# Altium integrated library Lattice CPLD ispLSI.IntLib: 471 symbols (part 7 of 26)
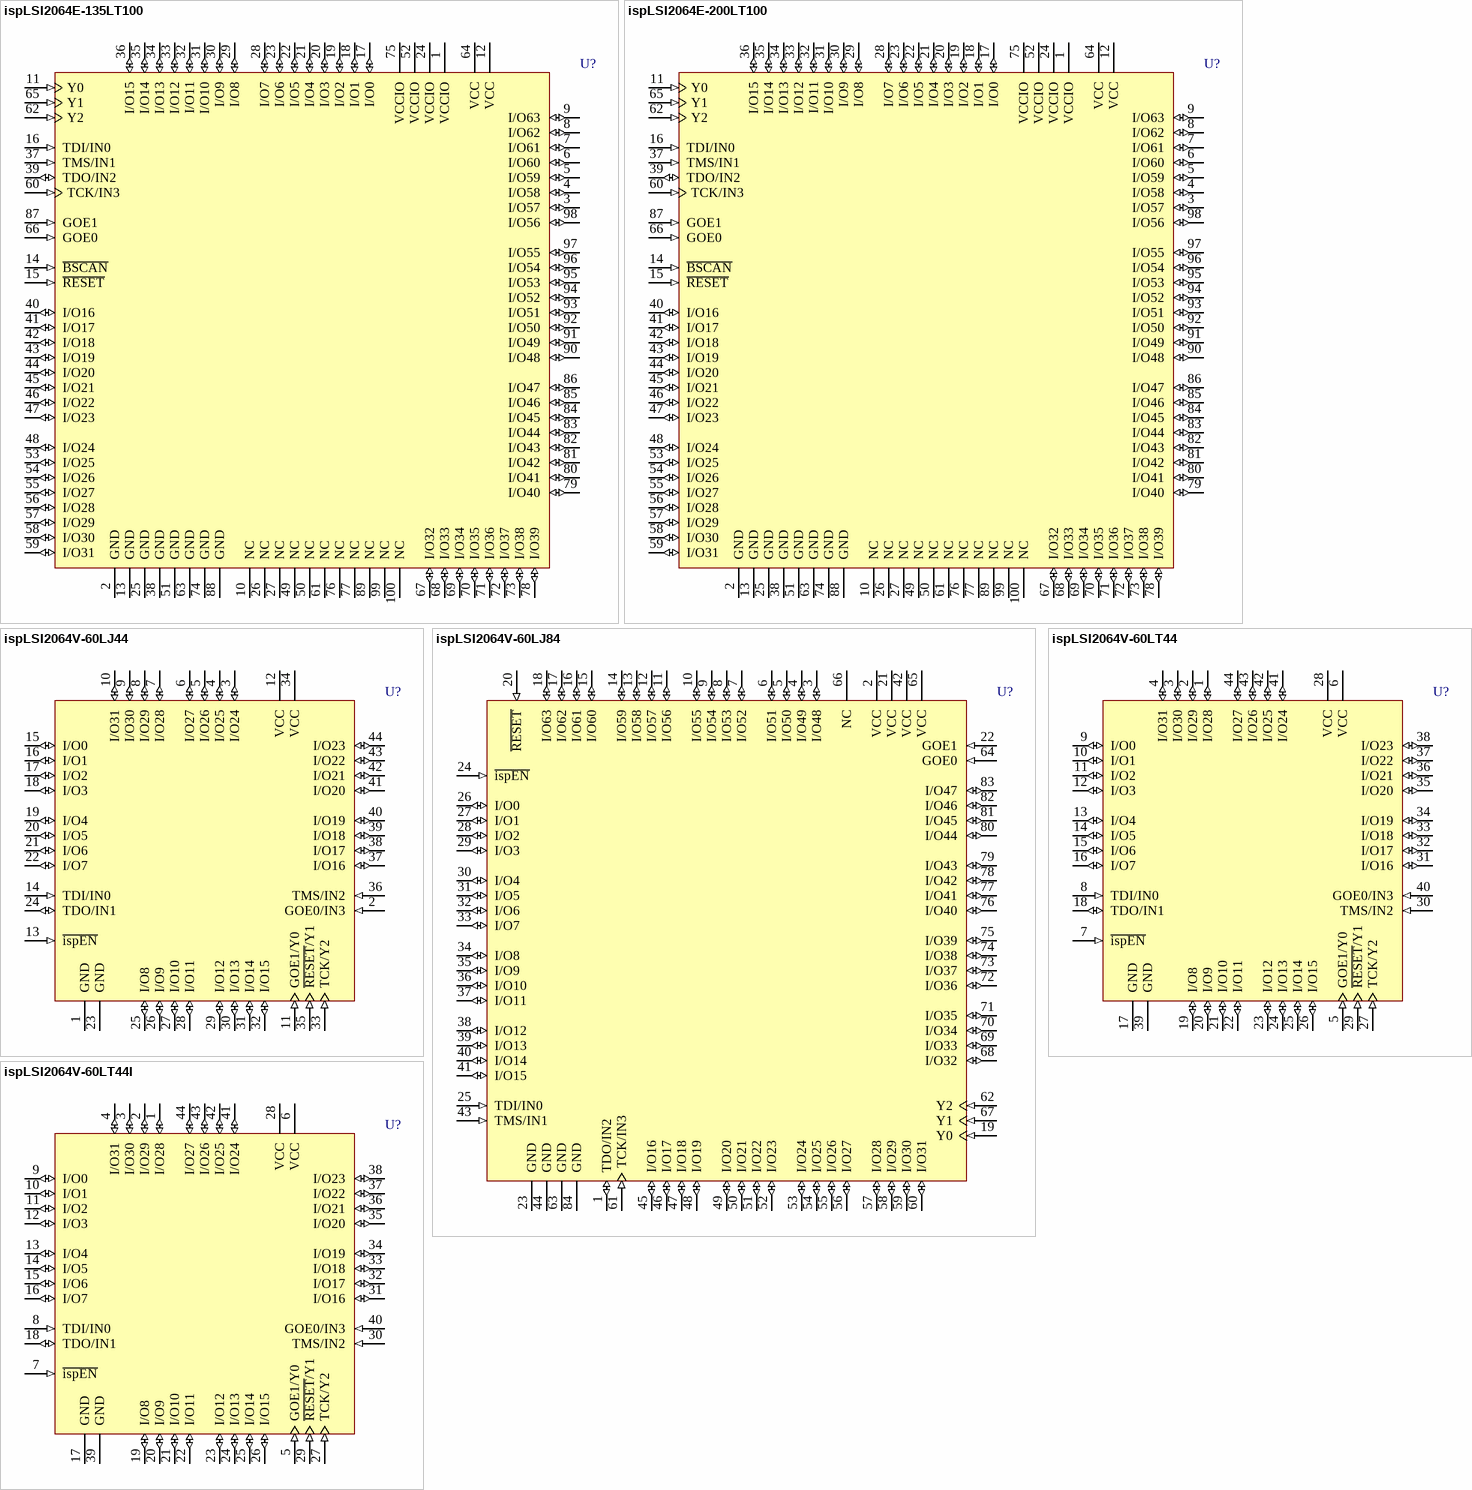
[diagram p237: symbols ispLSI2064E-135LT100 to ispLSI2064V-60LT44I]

## ispLSI2064E-200LT100
designator U?
In-System Programmable SuperFAST High Density PLD
footprint TQFP100_N (Thin QFP, 100-Leads, Body 14x14mm, Pitch 0.5mm, IPC Medium Density)
footprint TQFP100_L (Thin QFP, 100-Leads, Body 14x14mm, Pitch 0.5mm, IPC High Density)
footprint TQFP100_M (Thin QFP, 100-Leads, Body 14x14mm, Pitch 0.5mm, IPC Low Density)
3D model 2064E-TQFP100 (100-Pin Thin Quad Flat Pack (TQFP100))
pins: 1 VCCIO (power), 2 GND (power), 3 I/O57 (io), 4 I/O58 (io), 5 I/O59 (io), 6 I/O60 (io), 7 I/O61 (io), 8 I/O62 (io), 9 I/O63 (io), 10 NC, 11 Y0 (in), 12 VCC (power), 13 GND (power), 14 ~{BSCAN} (in), 15 ~{RESET} (in), 16 TDI/IN0 (in), 17 I/O0 (io), 18 I/O1 (io), 19 I/O2 (io), 20 I/O3 (io), 21 I/O4 (io), 22 I/O5 (io), 23 I/O6 (io), 24 VCCIO (power), 25 GND (power), 26 NC, 27 NC, 28 I/O7 (io), 29 I/O8 (io), 30 I/O9 (io), 31 I/O10 (io), 32 I/O11 (io), 33 I/O12 (io), 34 I/O13 (io), 35 I/O14 (io), 36 I/O15 (io), 37 TMS/IN1 (in), 38 GND (power), 39 TDO/IN2 (io), 40 I/O16 (io), 41 I/O17 (io), 42 I/O18 (io), 43 I/O19 (io), 44 I/O20 (io), 45 I/O21 (io), 46 I/O22 (io), 47 I/O23 (io), 48 I/O24 (io), 49 NC, 50 NC, 51 GND (power), 52 VCCIO (power), 53 I/O25 (io), 54 I/O26 (io), 55 I/O27 (io), 56 I/O28 (io), 57 I/O29 (io), 58 I/O30 (io), 59 I/O31 (io), 60 TCK/IN3 (in), 61 NC, 62 Y2 (in), 63 GND (power), 64 VCC (power), 65 Y1 (in), 66 GOE0 (in), 67 I/O32 (io), 68 I/O33 (io), 69 I/O34 (io), 70 I/O35 (io), 71 I/O36 (io), 72 I/O37 (io), 73 I/O38 (io), 74 GND (power), 75 VCCIO (power), 76 NC, 77 NC, 78 I/O39 (io), 79 I/O40 (io), 80 I/O41 (io), 81 I/O42 (io), 82 I/O43 (io), 83 I/O44 (io), 84 I/O45 (io), 85 I/O46 (io), 86 I/O47 (io), 87 GOE1 (in), 88 GND (power), 89 NC, 90 I/O48 (io), 91 I/O49 (io), 92 I/O50 (io), 93 I/O51 (io), 94 I/O52 (io), 95 I/O53 (io), 96 I/O54 (io), 97 I/O55 (io), 98 I/O56 (io), 99 NC, 100 NC

## ispLSI2064V-60LJ44
designator U?
3.3V High-Density Programmable Logic
footprint PLCC44_N (Leaded Chip Carrier, 44-Leads, Body 16.6x16.6mm, Pitch 1.27mm, IPC Medium Density)
footprint PLCC44_L (Leaded Chip Carrier, 44-Leads, Body 16.6x16.6mm, Pitch 1.27mm, IPC High Density)
footprint PLCC44_M (Leaded Chip Carrier, 44-Leads, Body 16.6x16.6mm, Pitch 1.27mm, IPC Low Density)
3D model 2064V-PLCC44 (44-Pin Leaded Chip Carrier 1.27 mm Pitch)
pins: 1 GND (power), 2 GOE0/IN3 (in), 3 I/O24 (io), 4 I/O25 (io), 5 I/O26 (io), 6 I/O27 (io), 7 I/O28 (io), 8 I/O29 (io), 9 I/O30 (io), 10 I/O31 (io), 11 GOE1/Y0 (in), 12 VCC (power), 13 ~{ispEN} (in), 14 TDI/IN0 (in), 15 I/O0 (io), 16 I/O1 (io), 17 I/O2 (io), 18 I/O3 (io), 19 I/O4 (io), 20 I/O5 (io), 21 I/O6 (io), 22 I/O7 (io), 23 GND (power), 24 TDO/IN1 (io), 25 I/O8 (io), 26 I/O9 (io), 27 I/O10 (io), 28 I/O11 (io), 29 I/O12 (io), 30 I/O13 (io), 31 I/O14 (io), 32 I/O15 (io), 33 TCK/Y2 (in), 34 VCC (power), 35 ~{RESET}/Y1 (in), 36 TMS/IN2 (in), 37 I/O16 (io), 38 I/O17 (io), 39 I/O18 (io), 40 I/O19 (io), 41 I/O20 (io), 42 I/O21 (io), 43 I/O22 (io), 44 I/O23 (io)

## ispLSI2064V-60LJ84
designator U?
3.3V High-Density Programmable Logic
footprint PLCC84_N (Leaded Chip Carrier, 84-Leads, Body 29.3x29.3mm, Pitch 1.27mm, IPC Medium Density)
footprint PLCC84_L (Leaded Chip Carrier, 84-Leads, Body 29.3x29.3mm, Pitch 1.27mm, IPC High Density)
footprint PLCC84_M (Leaded Chip Carrier, 84-Leads, Body 29.3x29.3mm, Pitch 1.27mm, IPC Low Density)
3D model 2064V-PLCC84 (84-Pin Leaded Chip Carrier 1.27 mm Pitch)
pins: 1 TDO/IN2 (io), 2 VCC (power), 3 I/O48 (io), 4 I/O49 (io), 5 I/O50 (io), 6 I/O51 (io), 7 I/O52 (io), 8 I/O53 (io), 9 I/O54 (io), 10 I/O55 (io), 11 I/O56 (io), 12 I/O57 (io), 13 I/O58 (io), 14 I/O59 (io), 15 I/O60 (io), 16 I/O61 (io), 17 I/O62 (io), 18 I/O63 (io), 19 Y0 (in), 20 ~{RESET} (in), 21 VCC (power), 22 GOE1 (in), 23 GND (power), 24 ~{isp}~{EN} (in), 25 TDI/IN0 (in), 26 I/O0 (io), 27 I/O1 (io), 28 I/O2 (io), 29 I/O3 (io), 30 I/O4 (io), 31 I/O5 (io), 32 I/O6 (io), 33 I/O7 (io), 34 I/O8 (io), 35 I/O9 (io), 36 I/O10 (io), 37 I/O11 (io), 38 I/O12 (io), 39 I/O13 (io), 40 I/O14 (io), 41 I/O15 (io), 42 VCC (power), 43 TMS/IN1 (in), 44 GND (power), 45 I/O16 (io), 46 I/O17 (io), 47 I/O18 (io), 48 I/O19 (io), 49 I/O20 (io), 50 I/O21 (io), 51 I/O22 (io), 52 I/O23 (io), 53 I/O24 (io), 54 I/O25 (io), 55 I/O26 (io), 56 I/O27 (io), 57 I/O28 (io), 58 I/O29 (io), 59 I/O30 (io), 60 I/O31 (io), 61 TCK/IN3 (in), 62 Y2 (in), 63 GND (power), 64 GOE0 (in), 65 VCC (power), 66 NC, 67 Y1 (in), 68 I/O32 (io), 69 I/O33 (io), 70 I/O34 (io), 71 I/O35 (io), 72 I/O36 (io), 73 I/O37 (io), 74 I/O38 (io), 75 I/O39 (io), 76 I/O40 (io), 77 I/O41 (io), 78 I/O42 (io), 79 I/O43 (io), 80 I/O44 (io), 81 I/O45 (io), 82 I/O46 (io), 83 I/O47 (io), 84 GND (power)

## ispLSI2064V-60LT44
designator U?
3.3V High-Density Programmable Logic
footprint TQFP44_N (Thin QFP, 44-Leads, Body 10x10mm, Pitch 0.8mm, IPC Medium Density)
footprint TQFP44_L (Thin QFP, 44-Leads, Body 10x10mm, Pitch 0.8mm, IPC High Density)
footprint TQFP44_M (Thin QFP, 44-Leads, Body 10x10mm, Pitch 0.8mm, IPC Low Density)
3D model 2064V-TQFP44 (44-Pin Thin Quad Flat Pack 0.8 mm Pitch)
pins: 1 I/O28 (io), 2 I/O29 (io), 3 I/O30 (io), 4 I/O31 (io), 5 GOE1/Y0 (in), 6 VCC (power), 7 ~{ispEN} (in), 8 TDI/IN0 (in), 9 I/O0 (io), 10 I/O1 (io), 11 I/O2 (io), 12 I/O3 (io), 13 I/O4 (io), 14 I/O5 (io), 15 I/O6 (io), 16 I/O7 (io), 17 GND (power), 18 TDO/IN1 (io), 19 I/O8 (io), 20 I/O9 (io), 21 I/O10 (io), 22 I/O11 (io), 23 I/O12 (io), 24 I/O13 (io), 25 I/O14 (io), 26 I/O15 (io), 27 TCK/Y2 (in), 28 VCC (power), 29 ~{RESET}/Y1 (in), 30 TMS/IN2 (in), 31 I/O16 (io), 32 I/O17 (io), 33 I/O18 (io), 34 I/O19 (io), 35 I/O20 (io), 36 I/O21 (io), 37 I/O22 (io), 38 I/O23 (io), 39 GND (power), 40 GOE0/IN3 (in), 41 I/O24 (io), 42 I/O25 (io), 43 I/O26 (io), 44 I/O27 (io)

## ispLSI2064V-60LT44I
designator U?
3.3V High-Density Programmable Logic
footprint TQFP44_N (Thin QFP, 44-Leads, Body 10x10mm, Pitch 0.8mm, IPC Medium Density)
footprint TQFP44_L (Thin QFP, 44-Leads, Body 10x10mm, Pitch 0.8mm, IPC High Density)
footprint TQFP44_M (Thin QFP, 44-Leads, Body 10x10mm, Pitch 0.8mm, IPC Low Density)
3D model 2064V-TQFP44 (44-Pin Thin Quad Flat Pack 0.8 mm Pitch)
pins: 1 I/O28 (io), 2 I/O29 (io), 3 I/O30 (io), 4 I/O31 (io), 5 GOE1/Y0 (in), 6 VCC (power), 7 ~{ispEN} (in), 8 TDI/IN0 (in), 9 I/O0 (io), 10 I/O1 (io), 11 I/O2 (io), 12 I/O3 (io), 13 I/O4 (io), 14 I/O5 (io), 15 I/O6 (io), 16 I/O7 (io), 17 GND (power), 18 TDO/IN1 (io), 19 I/O8 (io), 20 I/O9 (io), 21 I/O10 (io), 22 I/O11 (io), 23 I/O12 (io), 24 I/O13 (io), 25 I/O14 (io), 26 I/O15 (io), 27 TCK/Y2 (in), 28 VCC (power), 29 ~{RESET}/Y1 (in), 30 TMS/IN2 (in), 31 I/O16 (io), 32 I/O17 (io), 33 I/O18 (io), 34 I/O19 (io), 35 I/O20 (io), 36 I/O21 (io), 37 I/O22 (io), 38 I/O23 (io), 39 GND (power), 40 GOE0/IN3 (in), 41 I/O24 (io), 42 I/O25 (io), 43 I/O26 (io), 44 I/O27 (io)

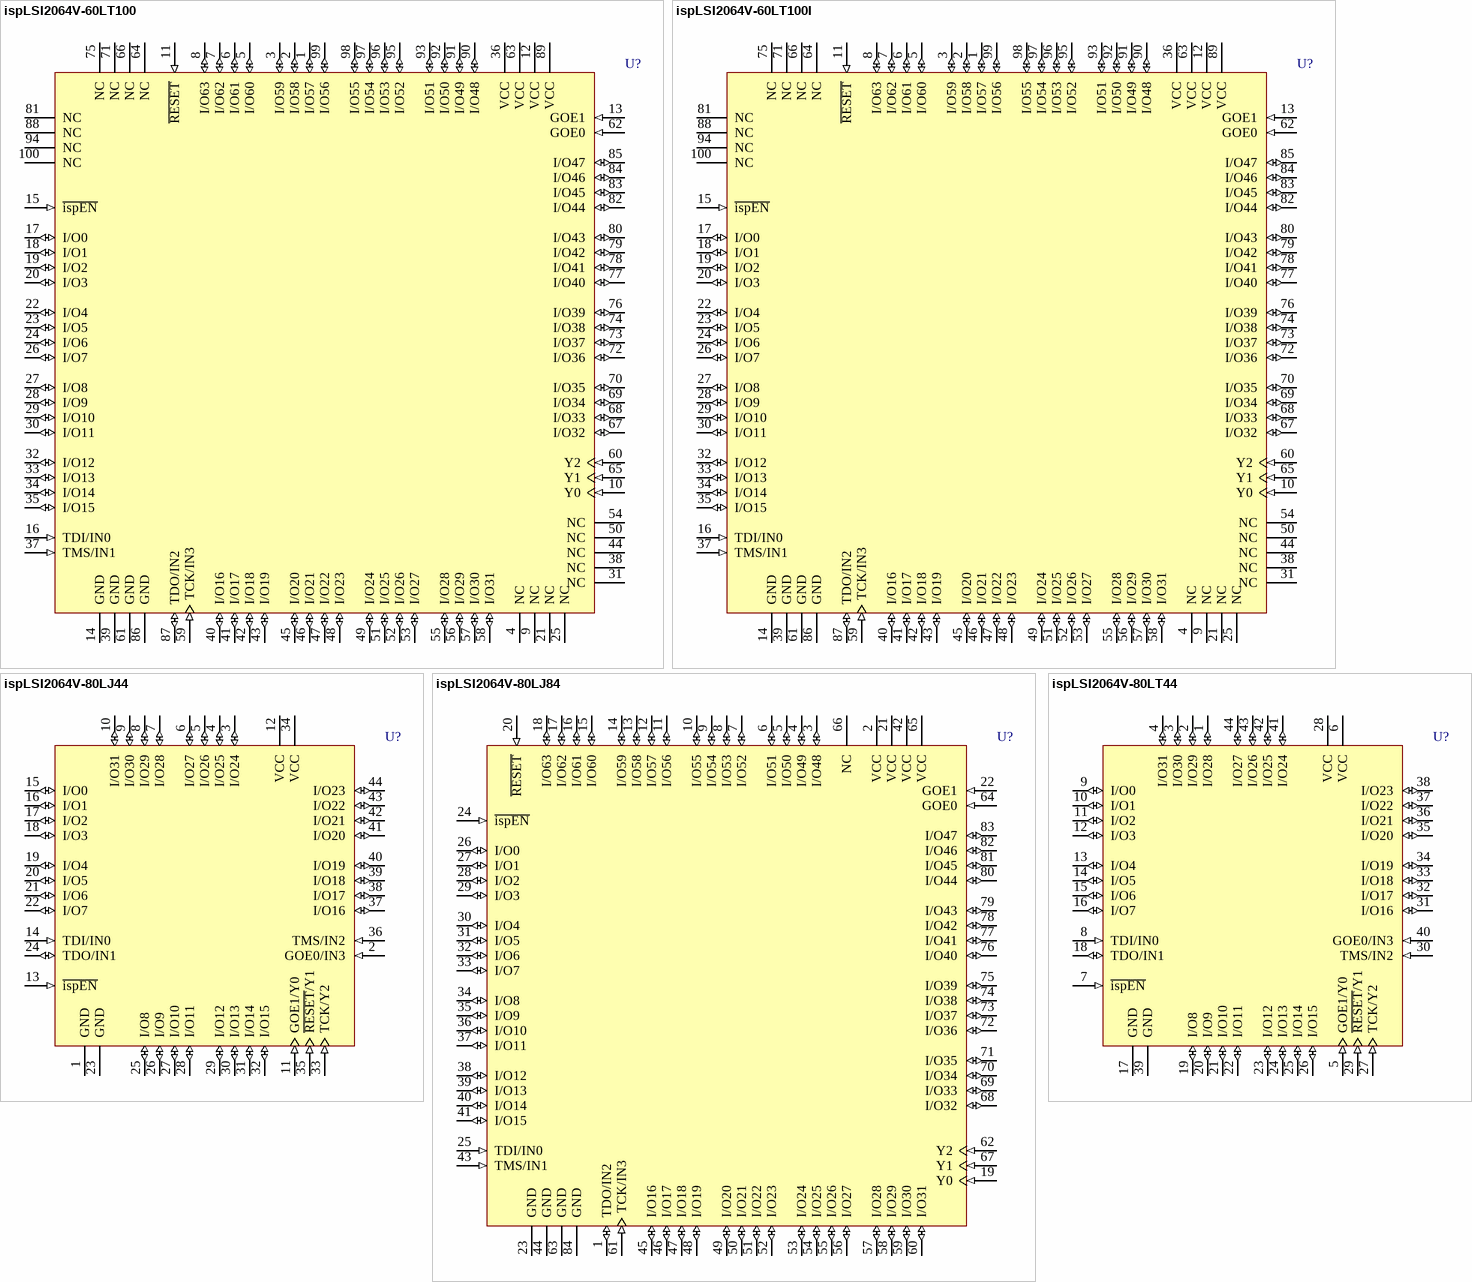
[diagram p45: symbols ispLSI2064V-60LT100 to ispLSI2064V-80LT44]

## ispLSI2064V-60LT100
designator U?
3.3V High-Density Programmable Logic
footprint TQFP100_N (Thin QFP, 100-Leads, Body 14x14mm, Pitch 0.5mm, IPC Medium Density)
footprint TQFP100_L (Thin QFP, 100-Leads, Body 14x14mm, Pitch 0.5mm, IPC High Density)
footprint TQFP100_M (Thin QFP, 100-Leads, Body 14x14mm, Pitch 0.5mm, IPC Low Density)
3D model 2064V-TQFP100 (100-Pin Thin Quad Flat Pack (TQFP100))
pins: 1 I/O57 (io), 2 I/O58 (io), 3 I/O59 (io), 4 NC, 5 I/O60 (io), 6 I/O61 (io), 7 I/O62 (io), 8 I/O63 (io), 9 NC, 10 Y0 (in), 11 ~{RESET} (in), 12 VCC (power), 13 GOE1 (in), 14 GND (power), 15 ~{ispEN} (in), 16 TDI/IN0 (in), 17 I/O0 (io), 18 I/O1 (io), 19 I/O2 (io), 20 I/O3 (io), 21 NC, 22 I/O4 (io), 23 I/O5 (io), 24 I/O6 (io), 25 NC, 26 I/O7 (io), 27 I/O8 (io), 28 I/O9 (io), 29 I/O10 (io), 30 I/O11 (io), 31 NC, 32 I/O12 (io), 33 I/O13 (io), 34 I/O14 (io), 35 I/O15 (io), 36 VCC (power), 37 TMS/IN1 (in), 38 NC, 39 GND (power), 40 I/O16 (io), 41 I/O17 (io), 42 I/O18 (io), 43 I/O19 (io), 44 NC, 45 I/O20 (io), 46 I/O21 (io), 47 I/O22 (io), 48 I/O23 (io), 49 I/O24 (io), 50 NC, 51 I/O25 (io), 52 I/O26 (io), 53 I/O27 (io), 54 NC, 55 I/O28 (io), 56 I/O29 (io), 57 I/O30 (io), 58 I/O31 (io), 59 TCK/IN3 (in), 60 Y2 (in), 61 GND (power), 62 GOE0 (in), 63 VCC (power), 64 NC, 65 Y1 (in), 66 NC, 67 I/O32 (io), 68 I/O33 (io), 69 I/O34 (io), 70 I/O35 (io), 71 NC, 72 I/O36 (io), 73 I/O37 (io), 74 I/O38 (io), 75 NC, 76 I/O39 (io), 77 I/O40 (io), 78 I/O41 (io), 79 I/O42 (io), 80 I/O43 (io), 81 NC, 82 I/O44 (io), 83 I/O45 (io), 84 I/O46 (io), 85 I/O47 (io), 86 GND (power), 87 TDO/IN2 (io), 88 NC, 89 VCC (power), 90 I/O48 (io), 91 I/O49 (io), 92 I/O50 (io), 93 I/O51 (io), 94 NC, 95 I/O52 (io), 96 I/O53 (io), 97 I/O54 (io), 98 I/O55 (io), 99 I/O56 (io), 100 NC

## ispLSI2064V-60LT100I
designator U?
3.3V High-Density Programmable Logic
footprint TQFP100_N (Thin QFP, 100-Leads, Body 14x14mm, Pitch 0.5mm, IPC Medium Density)
footprint TQFP100_L (Thin QFP, 100-Leads, Body 14x14mm, Pitch 0.5mm, IPC High Density)
footprint TQFP100_M (Thin QFP, 100-Leads, Body 14x14mm, Pitch 0.5mm, IPC Low Density)
3D model 2064V-TQFP100 (100-Pin Thin Quad Flat Pack (TQFP100))
pins: 1 I/O57 (io), 2 I/O58 (io), 3 I/O59 (io), 4 NC, 5 I/O60 (io), 6 I/O61 (io), 7 I/O62 (io), 8 I/O63 (io), 9 NC, 10 Y0 (in), 11 ~{RESET} (in), 12 VCC (power), 13 GOE1 (in), 14 GND (power), 15 ~{ispEN} (in), 16 TDI/IN0 (in), 17 I/O0 (io), 18 I/O1 (io), 19 I/O2 (io), 20 I/O3 (io), 21 NC, 22 I/O4 (io), 23 I/O5 (io), 24 I/O6 (io), 25 NC, 26 I/O7 (io), 27 I/O8 (io), 28 I/O9 (io), 29 I/O10 (io), 30 I/O11 (io), 31 NC, 32 I/O12 (io), 33 I/O13 (io), 34 I/O14 (io), 35 I/O15 (io), 36 VCC (power), 37 TMS/IN1 (in), 38 NC, 39 GND (power), 40 I/O16 (io), 41 I/O17 (io), 42 I/O18 (io), 43 I/O19 (io), 44 NC, 45 I/O20 (io), 46 I/O21 (io), 47 I/O22 (io), 48 I/O23 (io), 49 I/O24 (io), 50 NC, 51 I/O25 (io), 52 I/O26 (io), 53 I/O27 (io), 54 NC, 55 I/O28 (io), 56 I/O29 (io), 57 I/O30 (io), 58 I/O31 (io), 59 TCK/IN3 (in), 60 Y2 (in), 61 GND (power), 62 GOE0 (in), 63 VCC (power), 64 NC, 65 Y1 (in), 66 NC, 67 I/O32 (io), 68 I/O33 (io), 69 I/O34 (io), 70 I/O35 (io), 71 NC, 72 I/O36 (io), 73 I/O37 (io), 74 I/O38 (io), 75 NC, 76 I/O39 (io), 77 I/O40 (io), 78 I/O41 (io), 79 I/O42 (io), 80 I/O43 (io), 81 NC, 82 I/O44 (io), 83 I/O45 (io), 84 I/O46 (io), 85 I/O47 (io), 86 GND (power), 87 TDO/IN2 (io), 88 NC, 89 VCC (power), 90 I/O48 (io), 91 I/O49 (io), 92 I/O50 (io), 93 I/O51 (io), 94 NC, 95 I/O52 (io), 96 I/O53 (io), 97 I/O54 (io), 98 I/O55 (io), 99 I/O56 (io), 100 NC

## ispLSI2064V-80LJ44
designator U?
3.3V High-Density Programmable Logic
footprint PLCC44_N (Leaded Chip Carrier, 44-Leads, Body 16.6x16.6mm, Pitch 1.27mm, IPC Medium Density)
footprint PLCC44_L (Leaded Chip Carrier, 44-Leads, Body 16.6x16.6mm, Pitch 1.27mm, IPC High Density)
footprint PLCC44_M (Leaded Chip Carrier, 44-Leads, Body 16.6x16.6mm, Pitch 1.27mm, IPC Low Density)
3D model 2064V-PLCC44 (44-Pin Leaded Chip Carrier 1.27 mm Pitch)
pins: 1 GND (power), 2 GOE0/IN3 (in), 3 I/O24 (io), 4 I/O25 (io), 5 I/O26 (io), 6 I/O27 (io), 7 I/O28 (io), 8 I/O29 (io), 9 I/O30 (io), 10 I/O31 (io), 11 GOE1/Y0 (in), 12 VCC (power), 13 ~{ispEN} (in), 14 TDI/IN0 (in), 15 I/O0 (io), 16 I/O1 (io), 17 I/O2 (io), 18 I/O3 (io), 19 I/O4 (io), 20 I/O5 (io), 21 I/O6 (io), 22 I/O7 (io), 23 GND (power), 24 TDO/IN1 (io), 25 I/O8 (io), 26 I/O9 (io), 27 I/O10 (io), 28 I/O11 (io), 29 I/O12 (io), 30 I/O13 (io), 31 I/O14 (io), 32 I/O15 (io), 33 TCK/Y2 (in), 34 VCC (power), 35 ~{RESET}/Y1 (in), 36 TMS/IN2 (in), 37 I/O16 (io), 38 I/O17 (io), 39 I/O18 (io), 40 I/O19 (io), 41 I/O20 (io), 42 I/O21 (io), 43 I/O22 (io), 44 I/O23 (io)

## ispLSI2064V-80LJ84
designator U?
3.3V High-Density Programmable Logic
footprint PLCC84_N (Leaded Chip Carrier, 84-Leads, Body 29.3x29.3mm, Pitch 1.27mm, IPC Medium Density)
footprint PLCC84_L (Leaded Chip Carrier, 84-Leads, Body 29.3x29.3mm, Pitch 1.27mm, IPC High Density)
footprint PLCC84_M (Leaded Chip Carrier, 84-Leads, Body 29.3x29.3mm, Pitch 1.27mm, IPC Low Density)
3D model 2064V-PLCC84 (84-Pin Leaded Chip Carrier 1.27 mm Pitch)
pins: 1 TDO/IN2 (io), 2 VCC (power), 3 I/O48 (io), 4 I/O49 (io), 5 I/O50 (io), 6 I/O51 (io), 7 I/O52 (io), 8 I/O53 (io), 9 I/O54 (io), 10 I/O55 (io), 11 I/O56 (io), 12 I/O57 (io), 13 I/O58 (io), 14 I/O59 (io), 15 I/O60 (io), 16 I/O61 (io), 17 I/O62 (io), 18 I/O63 (io), 19 Y0 (in), 20 ~{RESET} (in), 21 VCC (power), 22 GOE1 (in), 23 GND (power), 24 ~{isp}~{EN} (in), 25 TDI/IN0 (in), 26 I/O0 (io), 27 I/O1 (io), 28 I/O2 (io), 29 I/O3 (io), 30 I/O4 (io), 31 I/O5 (io), 32 I/O6 (io), 33 I/O7 (io), 34 I/O8 (io), 35 I/O9 (io), 36 I/O10 (io), 37 I/O11 (io), 38 I/O12 (io), 39 I/O13 (io), 40 I/O14 (io), 41 I/O15 (io), 42 VCC (power), 43 TMS/IN1 (in), 44 GND (power), 45 I/O16 (io), 46 I/O17 (io), 47 I/O18 (io), 48 I/O19 (io), 49 I/O20 (io), 50 I/O21 (io), 51 I/O22 (io), 52 I/O23 (io), 53 I/O24 (io), 54 I/O25 (io), 55 I/O26 (io), 56 I/O27 (io), 57 I/O28 (io), 58 I/O29 (io), 59 I/O30 (io), 60 I/O31 (io), 61 TCK/IN3 (in), 62 Y2 (in), 63 GND (power), 64 GOE0 (in), 65 VCC (power), 66 NC, 67 Y1 (in), 68 I/O32 (io), 69 I/O33 (io), 70 I/O34 (io), 71 I/O35 (io), 72 I/O36 (io), 73 I/O37 (io), 74 I/O38 (io), 75 I/O39 (io), 76 I/O40 (io), 77 I/O41 (io), 78 I/O42 (io), 79 I/O43 (io), 80 I/O44 (io), 81 I/O45 (io), 82 I/O46 (io), 83 I/O47 (io), 84 GND (power)

## ispLSI2064V-80LT44
designator U?
3.3V High-Density Programmable Logic
footprint TQFP44_N (Thin QFP, 44-Leads, Body 10x10mm, Pitch 0.8mm, IPC Medium Density)
footprint TQFP44_L (Thin QFP, 44-Leads, Body 10x10mm, Pitch 0.8mm, IPC High Density)
footprint TQFP44_M (Thin QFP, 44-Leads, Body 10x10mm, Pitch 0.8mm, IPC Low Density)
3D model 2064V-TQFP44 (44-Pin Thin Quad Flat Pack 0.8 mm Pitch)
pins: 1 I/O28 (io), 2 I/O29 (io), 3 I/O30 (io), 4 I/O31 (io), 5 GOE1/Y0 (in), 6 VCC (power), 7 ~{ispEN} (in), 8 TDI/IN0 (in), 9 I/O0 (io), 10 I/O1 (io), 11 I/O2 (io), 12 I/O3 (io), 13 I/O4 (io), 14 I/O5 (io), 15 I/O6 (io), 16 I/O7 (io), 17 GND (power), 18 TDO/IN1 (io), 19 I/O8 (io), 20 I/O9 (io), 21 I/O10 (io), 22 I/O11 (io), 23 I/O12 (io), 24 I/O13 (io), 25 I/O14 (io), 26 I/O15 (io), 27 TCK/Y2 (in), 28 VCC (power), 29 ~{RESET}/Y1 (in), 30 TMS/IN2 (in), 31 I/O16 (io), 32 I/O17 (io), 33 I/O18 (io), 34 I/O19 (io), 35 I/O20 (io), 36 I/O21 (io), 37 I/O22 (io), 38 I/O23 (io), 39 GND (power), 40 GOE0/IN3 (in), 41 I/O24 (io), 42 I/O25 (io), 43 I/O26 (io), 44 I/O27 (io)

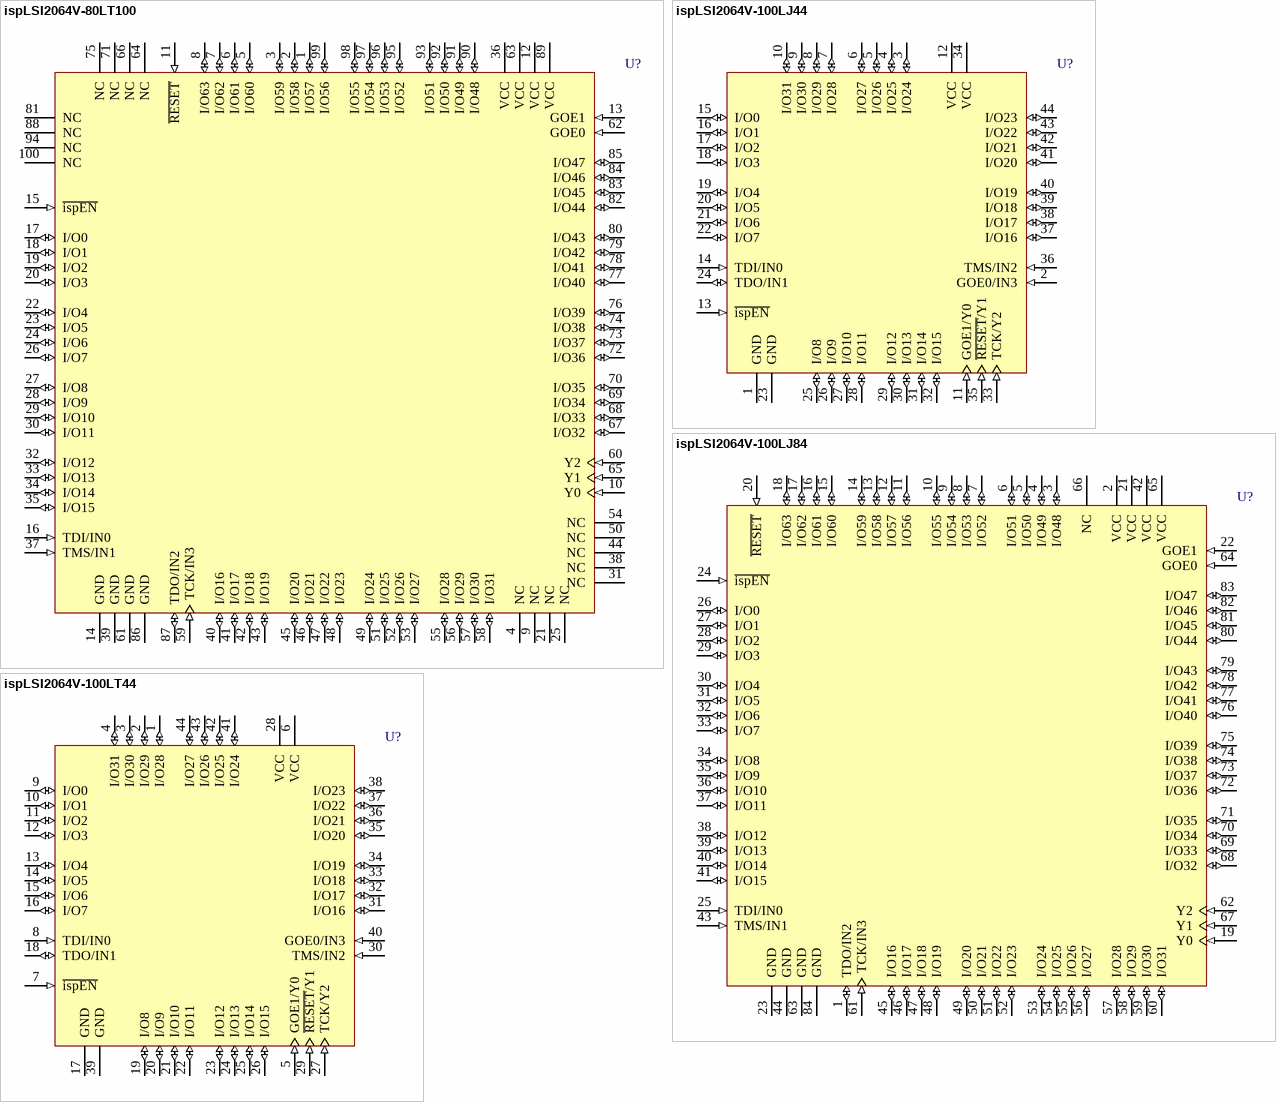
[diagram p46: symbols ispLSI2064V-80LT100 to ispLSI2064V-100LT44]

## ispLSI2064V-80LT100
designator U?
3.3V High-Density Programmable Logic
footprint TQFP100_N (Thin QFP, 100-Leads, Body 14x14mm, Pitch 0.5mm, IPC Medium Density)
footprint TQFP100_L (Thin QFP, 100-Leads, Body 14x14mm, Pitch 0.5mm, IPC High Density)
footprint TQFP100_M (Thin QFP, 100-Leads, Body 14x14mm, Pitch 0.5mm, IPC Low Density)
3D model 2064V-TQFP100 (100-Pin Thin Quad Flat Pack (TQFP100))
pins: 1 I/O57 (io), 2 I/O58 (io), 3 I/O59 (io), 4 NC, 5 I/O60 (io), 6 I/O61 (io), 7 I/O62 (io), 8 I/O63 (io), 9 NC, 10 Y0 (in), 11 ~{RESET} (in), 12 VCC (power), 13 GOE1 (in), 14 GND (power), 15 ~{ispEN} (in), 16 TDI/IN0 (in), 17 I/O0 (io), 18 I/O1 (io), 19 I/O2 (io), 20 I/O3 (io), 21 NC, 22 I/O4 (io), 23 I/O5 (io), 24 I/O6 (io), 25 NC, 26 I/O7 (io), 27 I/O8 (io), 28 I/O9 (io), 29 I/O10 (io), 30 I/O11 (io), 31 NC, 32 I/O12 (io), 33 I/O13 (io), 34 I/O14 (io), 35 I/O15 (io), 36 VCC (power), 37 TMS/IN1 (in), 38 NC, 39 GND (power), 40 I/O16 (io), 41 I/O17 (io), 42 I/O18 (io), 43 I/O19 (io), 44 NC, 45 I/O20 (io), 46 I/O21 (io), 47 I/O22 (io), 48 I/O23 (io), 49 I/O24 (io), 50 NC, 51 I/O25 (io), 52 I/O26 (io), 53 I/O27 (io), 54 NC, 55 I/O28 (io), 56 I/O29 (io), 57 I/O30 (io), 58 I/O31 (io), 59 TCK/IN3 (in), 60 Y2 (in), 61 GND (power), 62 GOE0 (in), 63 VCC (power), 64 NC, 65 Y1 (in), 66 NC, 67 I/O32 (io), 68 I/O33 (io), 69 I/O34 (io), 70 I/O35 (io), 71 NC, 72 I/O36 (io), 73 I/O37 (io), 74 I/O38 (io), 75 NC, 76 I/O39 (io), 77 I/O40 (io), 78 I/O41 (io), 79 I/O42 (io), 80 I/O43 (io), 81 NC, 82 I/O44 (io), 83 I/O45 (io), 84 I/O46 (io), 85 I/O47 (io), 86 GND (power), 87 TDO/IN2 (io), 88 NC, 89 VCC (power), 90 I/O48 (io), 91 I/O49 (io), 92 I/O50 (io), 93 I/O51 (io), 94 NC, 95 I/O52 (io), 96 I/O53 (io), 97 I/O54 (io), 98 I/O55 (io), 99 I/O56 (io), 100 NC

## ispLSI2064V-100LJ44
designator U?
3.3V High-Density Programmable Logic
footprint PLCC44_N (Leaded Chip Carrier, 44-Leads, Body 16.6x16.6mm, Pitch 1.27mm, IPC Medium Density)
footprint PLCC44_L (Leaded Chip Carrier, 44-Leads, Body 16.6x16.6mm, Pitch 1.27mm, IPC High Density)
footprint PLCC44_M (Leaded Chip Carrier, 44-Leads, Body 16.6x16.6mm, Pitch 1.27mm, IPC Low Density)
3D model 2064V-PLCC44 (44-Pin Leaded Chip Carrier 1.27 mm Pitch)
pins: 1 GND (power), 2 GOE0/IN3 (in), 3 I/O24 (io), 4 I/O25 (io), 5 I/O26 (io), 6 I/O27 (io), 7 I/O28 (io), 8 I/O29 (io), 9 I/O30 (io), 10 I/O31 (io), 11 GOE1/Y0 (in), 12 VCC (power), 13 ~{ispEN} (in), 14 TDI/IN0 (in), 15 I/O0 (io), 16 I/O1 (io), 17 I/O2 (io), 18 I/O3 (io), 19 I/O4 (io), 20 I/O5 (io), 21 I/O6 (io), 22 I/O7 (io), 23 GND (power), 24 TDO/IN1 (io), 25 I/O8 (io), 26 I/O9 (io), 27 I/O10 (io), 28 I/O11 (io), 29 I/O12 (io), 30 I/O13 (io), 31 I/O14 (io), 32 I/O15 (io), 33 TCK/Y2 (in), 34 VCC (power), 35 ~{RESET}/Y1 (in), 36 TMS/IN2 (in), 37 I/O16 (io), 38 I/O17 (io), 39 I/O18 (io), 40 I/O19 (io), 41 I/O20 (io), 42 I/O21 (io), 43 I/O22 (io), 44 I/O23 (io)

## ispLSI2064V-100LJ84
designator U?
3.3V High-Density Programmable Logic
footprint PLCC84_N (Leaded Chip Carrier, 84-Leads, Body 29.3x29.3mm, Pitch 1.27mm, IPC Medium Density)
footprint PLCC84_L (Leaded Chip Carrier, 84-Leads, Body 29.3x29.3mm, Pitch 1.27mm, IPC High Density)
footprint PLCC84_M (Leaded Chip Carrier, 84-Leads, Body 29.3x29.3mm, Pitch 1.27mm, IPC Low Density)
3D model 2064V-PLCC84 (84-Pin Leaded Chip Carrier 1.27 mm Pitch)
pins: 1 TDO/IN2 (io), 2 VCC (power), 3 I/O48 (io), 4 I/O49 (io), 5 I/O50 (io), 6 I/O51 (io), 7 I/O52 (io), 8 I/O53 (io), 9 I/O54 (io), 10 I/O55 (io), 11 I/O56 (io), 12 I/O57 (io), 13 I/O58 (io), 14 I/O59 (io), 15 I/O60 (io), 16 I/O61 (io), 17 I/O62 (io), 18 I/O63 (io), 19 Y0 (in), 20 ~{RESET} (in), 21 VCC (power), 22 GOE1 (in), 23 GND (power), 24 ~{isp}~{EN} (in), 25 TDI/IN0 (in), 26 I/O0 (io), 27 I/O1 (io), 28 I/O2 (io), 29 I/O3 (io), 30 I/O4 (io), 31 I/O5 (io), 32 I/O6 (io), 33 I/O7 (io), 34 I/O8 (io), 35 I/O9 (io), 36 I/O10 (io), 37 I/O11 (io), 38 I/O12 (io), 39 I/O13 (io), 40 I/O14 (io), 41 I/O15 (io), 42 VCC (power), 43 TMS/IN1 (in), 44 GND (power), 45 I/O16 (io), 46 I/O17 (io), 47 I/O18 (io), 48 I/O19 (io), 49 I/O20 (io), 50 I/O21 (io), 51 I/O22 (io), 52 I/O23 (io), 53 I/O24 (io), 54 I/O25 (io), 55 I/O26 (io), 56 I/O27 (io), 57 I/O28 (io), 58 I/O29 (io), 59 I/O30 (io), 60 I/O31 (io), 61 TCK/IN3 (in), 62 Y2 (in), 63 GND (power), 64 GOE0 (in), 65 VCC (power), 66 NC, 67 Y1 (in), 68 I/O32 (io), 69 I/O33 (io), 70 I/O34 (io), 71 I/O35 (io), 72 I/O36 (io), 73 I/O37 (io), 74 I/O38 (io), 75 I/O39 (io), 76 I/O40 (io), 77 I/O41 (io), 78 I/O42 (io), 79 I/O43 (io), 80 I/O44 (io), 81 I/O45 (io), 82 I/O46 (io), 83 I/O47 (io), 84 GND (power)

## ispLSI2064V-100LT44
designator U?
3.3V High-Density Programmable Logic
footprint TQFP44_N (Thin QFP, 44-Leads, Body 10x10mm, Pitch 0.8mm, IPC Medium Density)
footprint TQFP44_L (Thin QFP, 44-Leads, Body 10x10mm, Pitch 0.8mm, IPC High Density)
footprint TQFP44_M (Thin QFP, 44-Leads, Body 10x10mm, Pitch 0.8mm, IPC Low Density)
3D model 2064V-TQFP44 (44-Pin Thin Quad Flat Pack 0.8 mm Pitch)
pins: 1 I/O28 (io), 2 I/O29 (io), 3 I/O30 (io), 4 I/O31 (io), 5 GOE1/Y0 (in), 6 VCC (power), 7 ~{ispEN} (in), 8 TDI/IN0 (in), 9 I/O0 (io), 10 I/O1 (io), 11 I/O2 (io), 12 I/O3 (io), 13 I/O4 (io), 14 I/O5 (io), 15 I/O6 (io), 16 I/O7 (io), 17 GND (power), 18 TDO/IN1 (io), 19 I/O8 (io), 20 I/O9 (io), 21 I/O10 (io), 22 I/O11 (io), 23 I/O12 (io), 24 I/O13 (io), 25 I/O14 (io), 26 I/O15 (io), 27 TCK/Y2 (in), 28 VCC (power), 29 ~{RESET}/Y1 (in), 30 TMS/IN2 (in), 31 I/O16 (io), 32 I/O17 (io), 33 I/O18 (io), 34 I/O19 (io), 35 I/O20 (io), 36 I/O21 (io), 37 I/O22 (io), 38 I/O23 (io), 39 GND (power), 40 GOE0/IN3 (in), 41 I/O24 (io), 42 I/O25 (io), 43 I/O26 (io), 44 I/O27 (io)

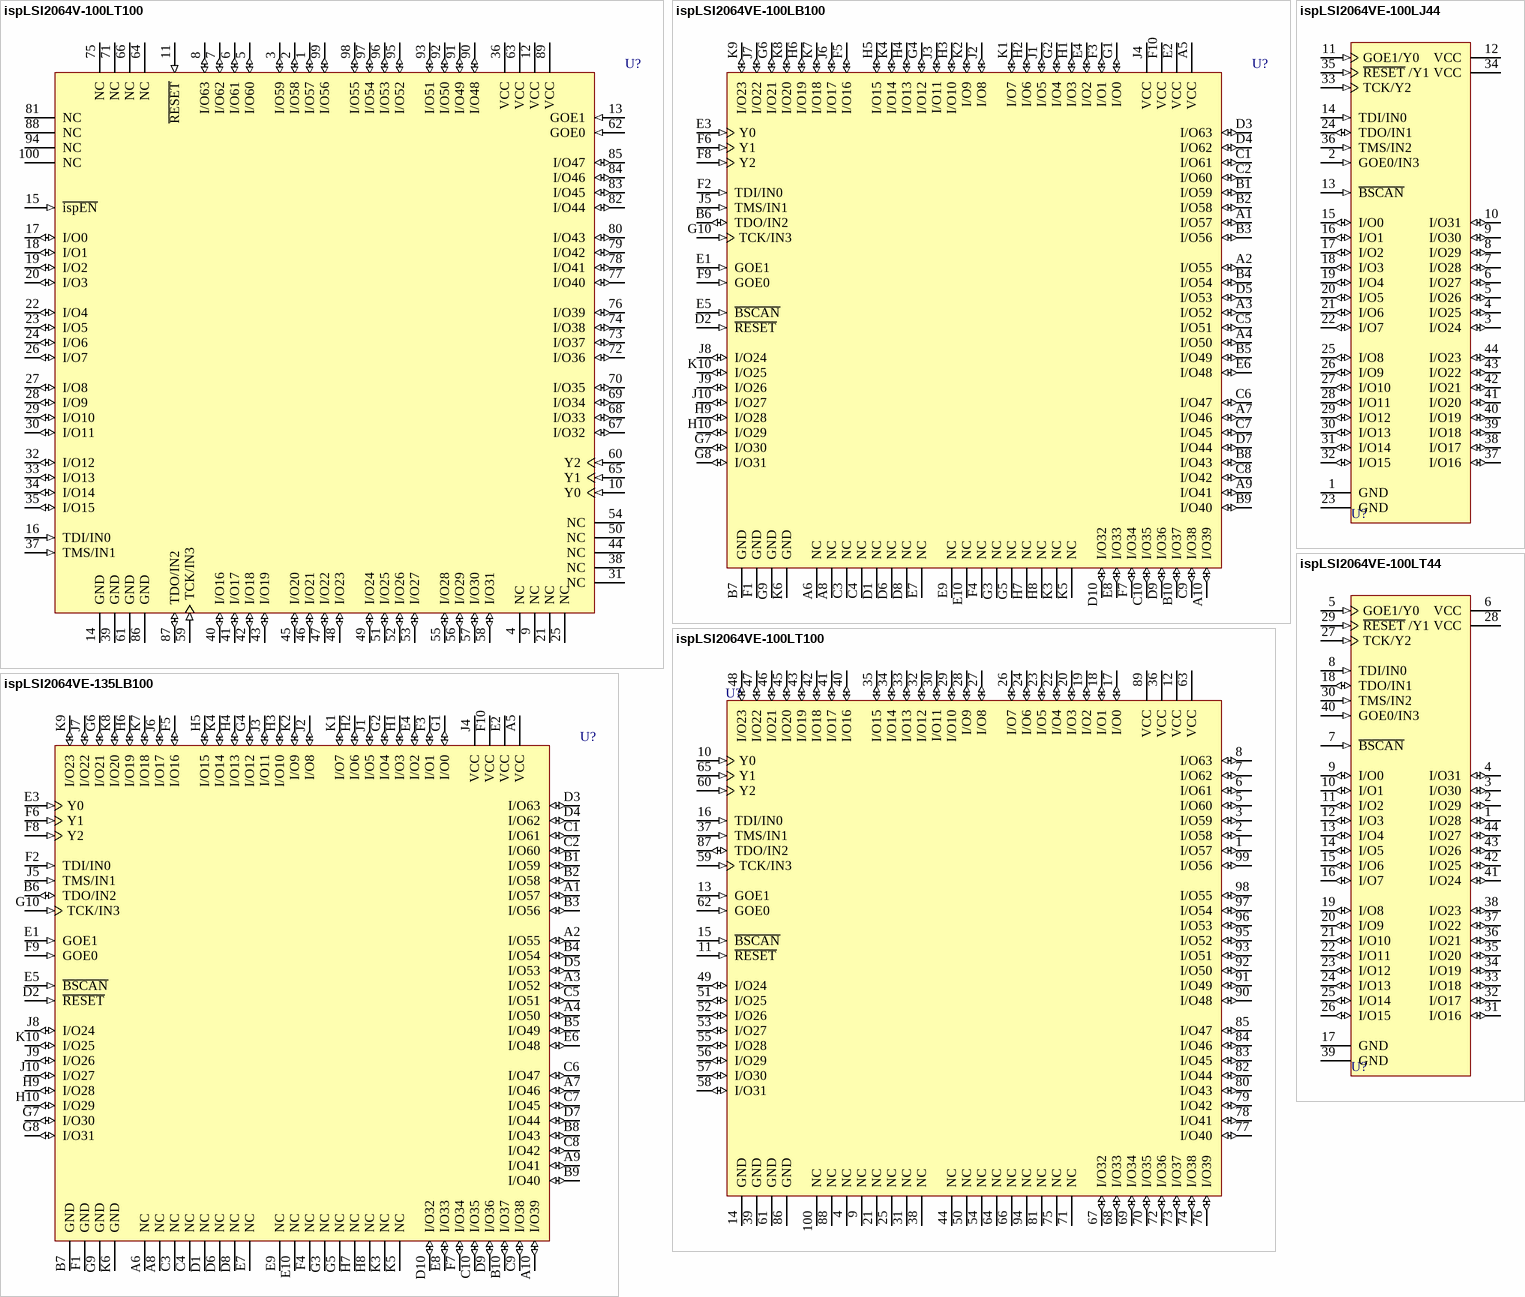
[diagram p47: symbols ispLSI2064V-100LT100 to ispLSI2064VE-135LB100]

## ispLSI2064V-100LT100
designator U?
3.3V High-Density Programmable Logic
footprint TQFP100_N (Thin QFP, 100-Leads, Body 14x14mm, Pitch 0.5mm, IPC Medium Density)
footprint TQFP100_L (Thin QFP, 100-Leads, Body 14x14mm, Pitch 0.5mm, IPC High Density)
footprint TQFP100_M (Thin QFP, 100-Leads, Body 14x14mm, Pitch 0.5mm, IPC Low Density)
3D model 2064V-TQFP100 (100-Pin Thin Quad Flat Pack (TQFP100))
pins: 1 I/O57 (io), 2 I/O58 (io), 3 I/O59 (io), 4 NC, 5 I/O60 (io), 6 I/O61 (io), 7 I/O62 (io), 8 I/O63 (io), 9 NC, 10 Y0 (in), 11 ~{RESET} (in), 12 VCC (power), 13 GOE1 (in), 14 GND (power), 15 ~{ispEN} (in), 16 TDI/IN0 (in), 17 I/O0 (io), 18 I/O1 (io), 19 I/O2 (io), 20 I/O3 (io), 21 NC, 22 I/O4 (io), 23 I/O5 (io), 24 I/O6 (io), 25 NC, 26 I/O7 (io), 27 I/O8 (io), 28 I/O9 (io), 29 I/O10 (io), 30 I/O11 (io), 31 NC, 32 I/O12 (io), 33 I/O13 (io), 34 I/O14 (io), 35 I/O15 (io), 36 VCC (power), 37 TMS/IN1 (in), 38 NC, 39 GND (power), 40 I/O16 (io), 41 I/O17 (io), 42 I/O18 (io), 43 I/O19 (io), 44 NC, 45 I/O20 (io), 46 I/O21 (io), 47 I/O22 (io), 48 I/O23 (io), 49 I/O24 (io), 50 NC, 51 I/O25 (io), 52 I/O26 (io), 53 I/O27 (io), 54 NC, 55 I/O28 (io), 56 I/O29 (io), 57 I/O30 (io), 58 I/O31 (io), 59 TCK/IN3 (in), 60 Y2 (in), 61 GND (power), 62 GOE0 (in), 63 VCC (power), 64 NC, 65 Y1 (in), 66 NC, 67 I/O32 (io), 68 I/O33 (io), 69 I/O34 (io), 70 I/O35 (io), 71 NC, 72 I/O36 (io), 73 I/O37 (io), 74 I/O38 (io), 75 NC, 76 I/O39 (io), 77 I/O40 (io), 78 I/O41 (io), 79 I/O42 (io), 80 I/O43 (io), 81 NC, 82 I/O44 (io), 83 I/O45 (io), 84 I/O46 (io), 85 I/O47 (io), 86 GND (power), 87 TDO/IN2 (io), 88 NC, 89 VCC (power), 90 I/O48 (io), 91 I/O49 (io), 92 I/O50 (io), 93 I/O51 (io), 94 NC, 95 I/O52 (io), 96 I/O53 (io), 97 I/O54 (io), 98 I/O55 (io), 99 I/O56 (io), 100 NC

## ispLSI2064VE-100LB100
designator U?
3.3V In-System Programmable High Density SuperFAST PLD
footprint caBGA100 (BGA, 100-Leads, Body 10x10mm, Pitch 0.8mm)
3D model 2064VE-caBGA100 (100-Ball Chip Array Ball Grid Array (caBGA100))
pins: A1 I/O57 (io), A2 I/O55 (io), A3 I/O52 (io), A4 I/O50 (io), A5 VCC (power), A6 NC, A7 I/O46 (io), A8 NC, A9 I/O41 (io), A10 I/O39 (io), B1 I/O59 (io), B2 I/O58 (io), B3 I/O56 (io), B4 I/O54 (io), B5 I/O49 (io), B6 TDO/IN2 (io), B7 GND (power), B8 I/O43 (io), B9 I/O40 (io), B10 I/O37 (io), C1 I/O61 (io), C2 I/O60 (io), C3 NC, C4 NC, C5 I/O51 (io), C6 I/O47 (io), C7 I/O45 (io), C8 I/O42 (io), C9 I/O38 (io), C10 I/O35 (io), D1 NC, D2 ~{RESET} (in), D3 I/O63 (io), D4 I/O62 (io), D5 I/O53 (io), D6 NC, D7 I/O44 (io), D8 NC, D9 I/O36 (io), D10 I/O32 (io), E1 GOE1 (in), E2 VCC (power), E3 Y0 (in), E4 I/O2 (io), E5 ~{BSCAN} (in), E6 I/O48 (io), E7 NC, E8 I/O33 (io), E9 NC, E10 NC, F1 GND (power), F2 TDI/IN0 (in), F3 I/O1 (io), F4 NC, F5 I/O16 (io), F6 Y1 (in), F7 I/O34 (io), F8 Y2 (in), F9 GOE0 (in), F10 VCC (power), G1 I/O0 (io), G2 I/O4 (io), G3 NC, G4 I/O12 (io), G5 NC, G6 I/O21 (io), G7 I/O30 (io), G8 I/O31 (io), G9 GND (power), G10 TCK/IN3 (in), H1 I/O3 (io), H2 I/O6 (io), H3 I/O10 (io), H4 I/O13 (io), H5 I/O15 (io), H6 I/O19 (io), H7 NC, H8 NC, H9 I/O28 (io), H10 I/O29 (io), J1 I/O5 (io), J2 I/O8 (io), J3 I/O11 (io), J4 VCC (power), J5 TMS/IN1 (in), J6 I/O17 (io), J7 I/O22 (io), J8 I/O24 (io), J9 I/O26 (io), J10 I/O27 (io), K1 I/O7 (io), K2 I/O9 (io), K3 NC, K4 I/O14 (io), K5 NC, K6 GND (power), K7 I/O18 (io), K8 I/O20 (io), K9 I/O23 (io), K10 I/O25 (io)

## ispLSI2064VE-100LJ44
designator U?
3.3V In-System Programmable High Density SuperFAST PLD
footprint PLCC44_N (Leaded Chip Carrier, 44-Leads, Body 16.6x16.6mm, Pitch 1.27mm, IPC Medium Density)
footprint PLCC44_L (Leaded Chip Carrier, 44-Leads, Body 16.6x16.6mm, Pitch 1.27mm, IPC High Density)
footprint PLCC44_M (Leaded Chip Carrier, 44-Leads, Body 16.6x16.6mm, Pitch 1.27mm, IPC Low Density)
3D model 2064VE-PLCC44 (44-Pin Leaded Chip Carrier 1.27 mm Pitch)
pins: 1 GND (power), 2 GOE0/IN3 (in), 3 I/O24 (io), 4 I/O25 (io), 5 I/O26 (io), 6 I/O27 (io), 7 I/O28 (io), 8 I/O29 (io), 9 I/O30 (io), 10 I/O31 (io), 11 GOE1/Y0 (in), 12 VCC (power), 13 ~{BSCAN} (in), 14 TDI/IN0 (in), 15 I/O0 (io), 16 I/O1 (io), 17 I/O2 (io), 18 I/O3 (io), 19 I/O4 (io), 20 I/O5 (io), 21 I/O6 (io), 22 I/O7 (io), 23 GND (power), 24 TDO/IN1 (io), 25 I/O8 (io), 26 I/O9 (io), 27 I/O10 (io), 28 I/O11 (io), 29 I/O12 (io), 30 I/O13 (io), 31 I/O14 (io), 32 I/O15 (io), 33 TCK/Y2 (in), 34 VCC (power), 35 ~{RESET} /Y1 (in), 36 TMS/IN2 (in), 37 I/O16 (io), 38 I/O17 (io), 39 I/O18 (io), 40 I/O19 (io), 41 I/O20 (io), 42 I/O21 (io), 43 I/O22 (io), 44 I/O23 (io)

## ispLSI2064VE-100LT44
designator U?
3.3V In-System Programmable High Density SuperFAST PLD
footprint TQFP44_N (Thin QFP, 44-Leads, Body 10x10mm, Pitch 0.8mm, IPC Medium Density)
footprint TQFP44_L (Thin QFP, 44-Leads, Body 10x10mm, Pitch 0.8mm, IPC High Density)
footprint TQFP44_M (Thin QFP, 44-Leads, Body 10x10mm, Pitch 0.8mm, IPC Low Density)
3D model 2064VE-TQFP44 (44-Pin Thin Quad Flat Pack 0.8 mm Pitch)
pins: 1 I/O28 (io), 2 I/O29 (io), 3 I/O30 (io), 4 I/O31 (io), 5 GOE1/Y0 (in), 6 VCC (power), 7 ~{BSCAN} (in), 8 TDI/IN0 (in), 9 I/O0 (io), 10 I/O1 (io), 11 I/O2 (io), 12 I/O3 (io), 13 I/O4 (io), 14 I/O5 (io), 15 I/O6 (io), 16 I/O7 (io), 17 GND (power), 18 TDO/IN1 (io), 19 I/O8 (io), 20 I/O9 (io), 21 I/O10 (io), 22 I/O11 (io), 23 I/O12 (io), 24 I/O13 (io), 25 I/O14 (io), 26 I/O15 (io), 27 TCK/Y2 (in), 28 VCC (power), 29 ~{RESET} /Y1 (in), 30 TMS/IN2 (in), 31 I/O16 (io), 32 I/O17 (io), 33 I/O18 (io), 34 I/O19 (io), 35 I/O20 (io), 36 I/O21 (io), 37 I/O22 (io), 38 I/O23 (io), 39 GND (power), 40 GOE0/IN3 (in), 41 I/O24 (io), 42 I/O25 (io), 43 I/O26 (io), 44 I/O27 (io)

## ispLSI2064VE-100LT100
designator U?
3.3V In-System Programmable High Density SuperFAST PLD
footprint TQFP100_N (Thin QFP, 100-Leads, Body 14x14mm, Pitch 0.5mm, IPC Medium Density)
footprint TQFP100_L (Thin QFP, 100-Leads, Body 14x14mm, Pitch 0.5mm, IPC High Density)
footprint TQFP100_M (Thin QFP, 100-Leads, Body 14x14mm, Pitch 0.5mm, IPC Low Density)
3D model 2064VE-TQFP100 (100-Pin Thin Quad Flat Pack (TQFP100))
pins: 1 I/O57 (io), 2 I/O58 (io), 3 I/O59 (io), 4 NC, 5 I/O60 (io), 6 I/O61 (io), 7 I/O62 (io), 8 I/O63 (io), 9 NC, 10 Y0 (in), 11 ~{RESET} (in), 12 VCC (power), 13 GOE1 (in), 14 GND (power), 15 ~{BSCAN} (in), 16 TDI/IN0 (in), 17 I/O0 (io), 18 I/O1 (io), 19 I/O2 (io), 20 I/O3 (io), 21 NC, 22 I/O4 (io), 23 I/O5 (io), 24 I/O6 (io), 25 NC, 26 I/O7 (io), 27 I/O8 (io), 28 I/O9 (io), 29 I/O10 (io), 30 I/O11 (io), 31 NC, 32 I/O12 (io), 33 I/O13 (io), 34 I/O14 (io), 35 I/O15 (io), 36 VCC (power), 37 TMS/IN1 (in), 38 NC, 39 GND (power), 40 I/O16 (io), 41 I/O17 (io), 42 I/O18 (io), 43 I/O19 (io), 44 NC, 45 I/O20 (io), 46 I/O21 (io), 47 I/O22 (io), 48 I/O23 (io), 49 I/O24 (io), 50 NC, 51 I/O25 (io), 52 I/O26 (io), 53 I/O27 (io), 54 NC, 55 I/O28 (io), 56 I/O29 (io), 57 I/O30 (io), 58 I/O31 (io), 59 TCK/IN3 (in), 60 Y2 (in), 61 GND (power), 62 GOE0 (in), 63 VCC (power), 64 NC, 65 Y1 (in), 66 NC, 67 I/O32 (io), 68 I/O33 (io), 69 I/O34 (io), 70 I/O35 (io), 71 NC, 72 I/O36 (io), 73 I/O37 (io), 74 I/O38 (io), 75 NC, 76 I/O39 (io), 77 I/O40 (io), 78 I/O41 (io), 79 I/O42 (io), 80 I/O43 (io), 81 NC, 82 I/O44 (io), 83 I/O45 (io), 84 I/O46 (io), 85 I/O47 (io), 86 GND (power), 87 TDO/IN2 (io), 88 NC, 89 VCC (power), 90 I/O48 (io), 91 I/O49 (io), 92 I/O50 (io), 93 I/O51 (io), 94 NC, 95 I/O52 (io), 96 I/O53 (io), 97 I/O54 (io), 98 I/O55 (io), 99 I/O56 (io), 100 NC

## ispLSI2064VE-135LB100
designator U?
3.3V In-System Programmable High Density SuperFAST PLD
footprint caBGA100 (BGA, 100-Leads, Body 10x10mm, Pitch 0.8mm)
3D model 2064VE-caBGA100 (100-Ball Chip Array Ball Grid Array (caBGA100))
pins: A1 I/O57 (io), A2 I/O55 (io), A3 I/O52 (io), A4 I/O50 (io), A5 VCC (power), A6 NC, A7 I/O46 (io), A8 NC, A9 I/O41 (io), A10 I/O39 (io), B1 I/O59 (io), B2 I/O58 (io), B3 I/O56 (io), B4 I/O54 (io), B5 I/O49 (io), B6 TDO/IN2 (io), B7 GND (power), B8 I/O43 (io), B9 I/O40 (io), B10 I/O37 (io), C1 I/O61 (io), C2 I/O60 (io), C3 NC, C4 NC, C5 I/O51 (io), C6 I/O47 (io), C7 I/O45 (io), C8 I/O42 (io), C9 I/O38 (io), C10 I/O35 (io), D1 NC, D2 ~{RESET} (in), D3 I/O63 (io), D4 I/O62 (io), D5 I/O53 (io), D6 NC, D7 I/O44 (io), D8 NC, D9 I/O36 (io), D10 I/O32 (io), E1 GOE1 (in), E2 VCC (power), E3 Y0 (in), E4 I/O2 (io), E5 ~{BSCAN} (in), E6 I/O48 (io), E7 NC, E8 I/O33 (io), E9 NC, E10 NC, F1 GND (power), F2 TDI/IN0 (in), F3 I/O1 (io), F4 NC, F5 I/O16 (io), F6 Y1 (in), F7 I/O34 (io), F8 Y2 (in), F9 GOE0 (in), F10 VCC (power), G1 I/O0 (io), G2 I/O4 (io), G3 NC, G4 I/O12 (io), G5 NC, G6 I/O21 (io), G7 I/O30 (io), G8 I/O31 (io), G9 GND (power), G10 TCK/IN3 (in), H1 I/O3 (io), H2 I/O6 (io), H3 I/O10 (io), H4 I/O13 (io), H5 I/O15 (io), H6 I/O19 (io), H7 NC, H8 NC, H9 I/O28 (io), H10 I/O29 (io), J1 I/O5 (io), J2 I/O8 (io), J3 I/O11 (io), J4 VCC (power), J5 TMS/IN1 (in), J6 I/O17 (io), J7 I/O22 (io), J8 I/O24 (io), J9 I/O26 (io), J10 I/O27 (io), K1 I/O7 (io), K2 I/O9 (io), K3 NC, K4 I/O14 (io), K5 NC, K6 GND (power), K7 I/O18 (io), K8 I/O20 (io), K9 I/O23 (io), K10 I/O25 (io)

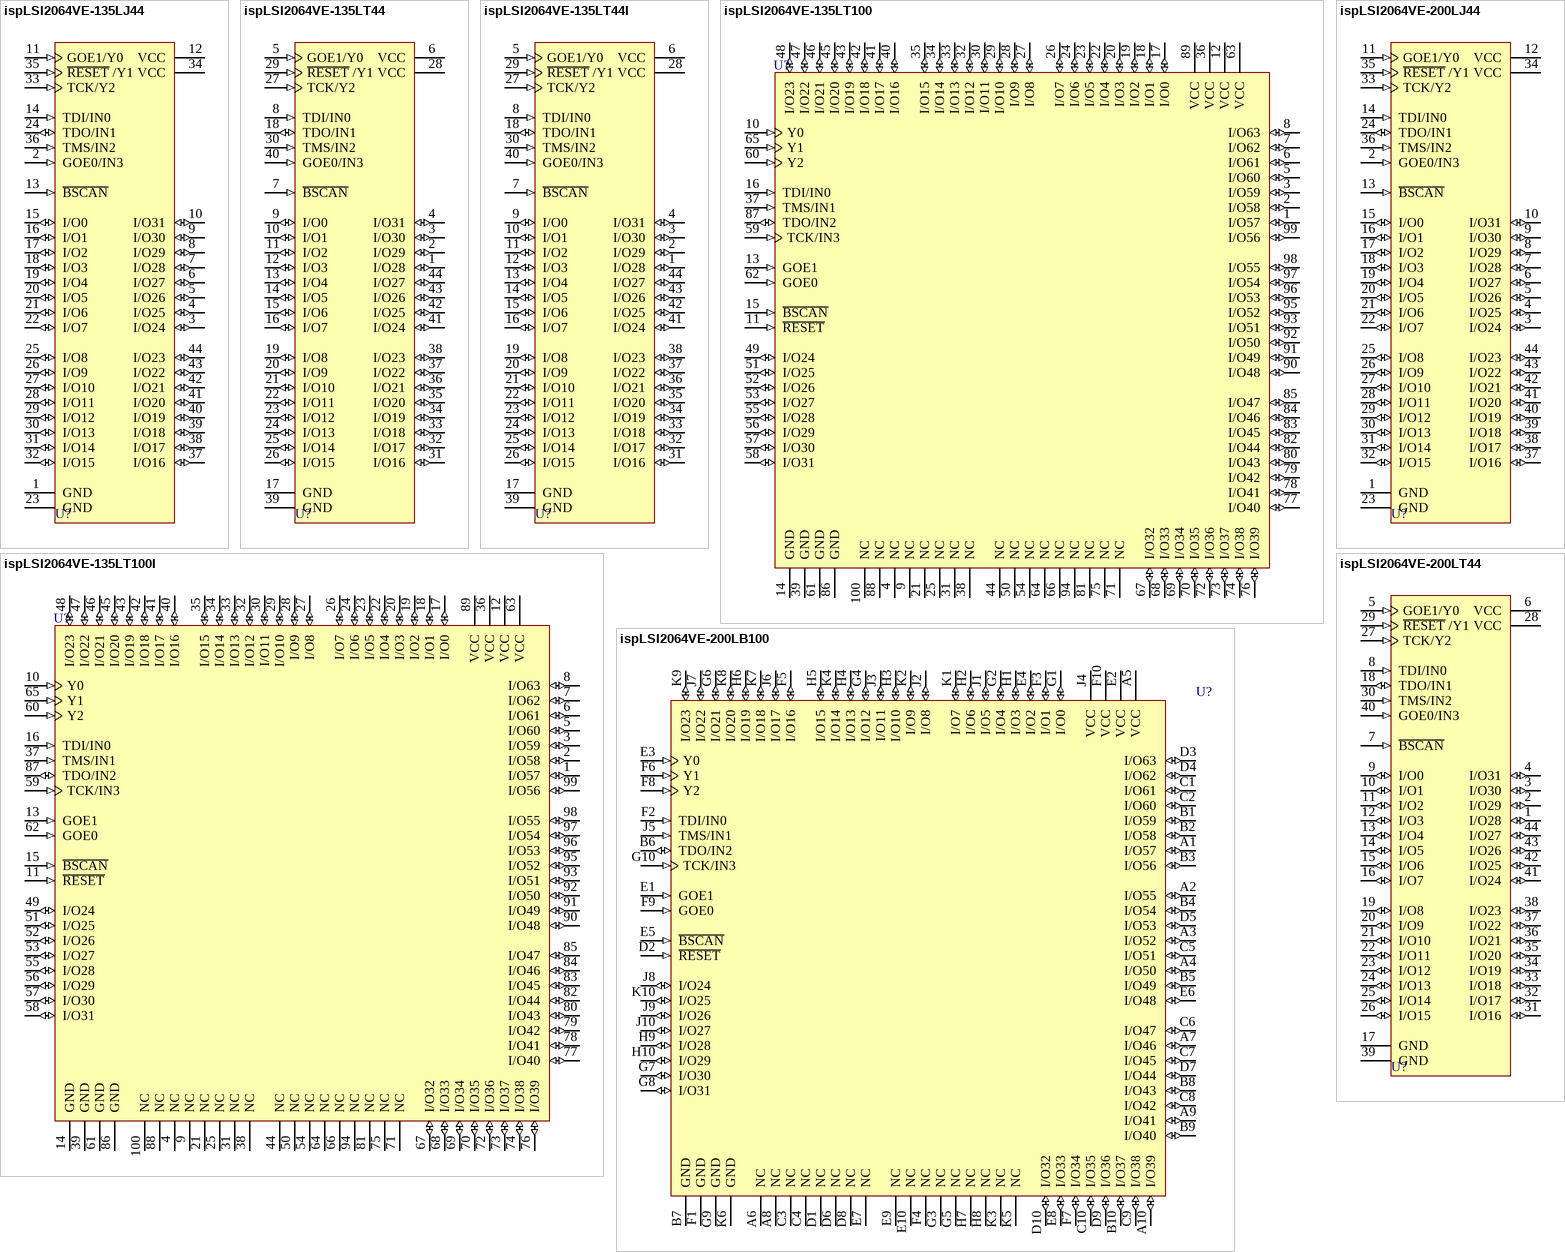
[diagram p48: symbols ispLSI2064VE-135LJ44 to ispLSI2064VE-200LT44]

## ispLSI2064VE-135LJ44
designator U?
3.3V In-System Programmable High Density SuperFAST PLD
footprint PLCC44_N (Leaded Chip Carrier, 44-Leads, Body 16.6x16.6mm, Pitch 1.27mm, IPC Medium Density)
footprint PLCC44_L (Leaded Chip Carrier, 44-Leads, Body 16.6x16.6mm, Pitch 1.27mm, IPC High Density)
footprint PLCC44_M (Leaded Chip Carrier, 44-Leads, Body 16.6x16.6mm, Pitch 1.27mm, IPC Low Density)
3D model 2064VE-PLCC44 (44-Pin Leaded Chip Carrier 1.27 mm Pitch)
pins: 1 GND (power), 2 GOE0/IN3 (in), 3 I/O24 (io), 4 I/O25 (io), 5 I/O26 (io), 6 I/O27 (io), 7 I/O28 (io), 8 I/O29 (io), 9 I/O30 (io), 10 I/O31 (io), 11 GOE1/Y0 (in), 12 VCC (power), 13 ~{BSCAN} (in), 14 TDI/IN0 (in), 15 I/O0 (io), 16 I/O1 (io), 17 I/O2 (io), 18 I/O3 (io), 19 I/O4 (io), 20 I/O5 (io), 21 I/O6 (io), 22 I/O7 (io), 23 GND (power), 24 TDO/IN1 (io), 25 I/O8 (io), 26 I/O9 (io), 27 I/O10 (io), 28 I/O11 (io), 29 I/O12 (io), 30 I/O13 (io), 31 I/O14 (io), 32 I/O15 (io), 33 TCK/Y2 (in), 34 VCC (power), 35 ~{RESET} /Y1 (in), 36 TMS/IN2 (in), 37 I/O16 (io), 38 I/O17 (io), 39 I/O18 (io), 40 I/O19 (io), 41 I/O20 (io), 42 I/O21 (io), 43 I/O22 (io), 44 I/O23 (io)

## ispLSI2064VE-135LT44
designator U?
3.3V In-System Programmable High Density SuperFAST PLD
footprint TQFP44_N (Thin QFP, 44-Leads, Body 10x10mm, Pitch 0.8mm, IPC Medium Density)
footprint TQFP44_L (Thin QFP, 44-Leads, Body 10x10mm, Pitch 0.8mm, IPC High Density)
footprint TQFP44_M (Thin QFP, 44-Leads, Body 10x10mm, Pitch 0.8mm, IPC Low Density)
3D model 2064VE-TQFP44 (44-Pin Thin Quad Flat Pack 0.8 mm Pitch)
pins: 1 I/O28 (io), 2 I/O29 (io), 3 I/O30 (io), 4 I/O31 (io), 5 GOE1/Y0 (in), 6 VCC (power), 7 ~{BSCAN} (in), 8 TDI/IN0 (in), 9 I/O0 (io), 10 I/O1 (io), 11 I/O2 (io), 12 I/O3 (io), 13 I/O4 (io), 14 I/O5 (io), 15 I/O6 (io), 16 I/O7 (io), 17 GND (power), 18 TDO/IN1 (io), 19 I/O8 (io), 20 I/O9 (io), 21 I/O10 (io), 22 I/O11 (io), 23 I/O12 (io), 24 I/O13 (io), 25 I/O14 (io), 26 I/O15 (io), 27 TCK/Y2 (in), 28 VCC (power), 29 ~{RESET} /Y1 (in), 30 TMS/IN2 (in), 31 I/O16 (io), 32 I/O17 (io), 33 I/O18 (io), 34 I/O19 (io), 35 I/O20 (io), 36 I/O21 (io), 37 I/O22 (io), 38 I/O23 (io), 39 GND (power), 40 GOE0/IN3 (in), 41 I/O24 (io), 42 I/O25 (io), 43 I/O26 (io), 44 I/O27 (io)

## ispLSI2064VE-135LT44I
designator U?
3.3V In-System Programmable High Density SuperFAST PLD
footprint TQFP44_N (Thin QFP, 44-Leads, Body 10x10mm, Pitch 0.8mm, IPC Medium Density)
footprint TQFP44_L (Thin QFP, 44-Leads, Body 10x10mm, Pitch 0.8mm, IPC High Density)
footprint TQFP44_M (Thin QFP, 44-Leads, Body 10x10mm, Pitch 0.8mm, IPC Low Density)
3D model 2064VE-TQFP44 (44-Pin Thin Quad Flat Pack 0.8 mm Pitch)
pins: 1 I/O28 (io), 2 I/O29 (io), 3 I/O30 (io), 4 I/O31 (io), 5 GOE1/Y0 (in), 6 VCC (power), 7 ~{BSCAN} (in), 8 TDI/IN0 (in), 9 I/O0 (io), 10 I/O1 (io), 11 I/O2 (io), 12 I/O3 (io), 13 I/O4 (io), 14 I/O5 (io), 15 I/O6 (io), 16 I/O7 (io), 17 GND (power), 18 TDO/IN1 (io), 19 I/O8 (io), 20 I/O9 (io), 21 I/O10 (io), 22 I/O11 (io), 23 I/O12 (io), 24 I/O13 (io), 25 I/O14 (io), 26 I/O15 (io), 27 TCK/Y2 (in), 28 VCC (power), 29 ~{RESET} /Y1 (in), 30 TMS/IN2 (in), 31 I/O16 (io), 32 I/O17 (io), 33 I/O18 (io), 34 I/O19 (io), 35 I/O20 (io), 36 I/O21 (io), 37 I/O22 (io), 38 I/O23 (io), 39 GND (power), 40 GOE0/IN3 (in), 41 I/O24 (io), 42 I/O25 (io), 43 I/O26 (io), 44 I/O27 (io)

## ispLSI2064VE-135LT100
designator U?
3.3V In-System Programmable High Density SuperFAST PLD
footprint TQFP100_N (Thin QFP, 100-Leads, Body 14x14mm, Pitch 0.5mm, IPC Medium Density)
footprint TQFP100_L (Thin QFP, 100-Leads, Body 14x14mm, Pitch 0.5mm, IPC High Density)
footprint TQFP100_M (Thin QFP, 100-Leads, Body 14x14mm, Pitch 0.5mm, IPC Low Density)
3D model 2064VE-TQFP100 (100-Pin Thin Quad Flat Pack (TQFP100))
pins: 1 I/O57 (io), 2 I/O58 (io), 3 I/O59 (io), 4 NC, 5 I/O60 (io), 6 I/O61 (io), 7 I/O62 (io), 8 I/O63 (io), 9 NC, 10 Y0 (in), 11 ~{RESET} (in), 12 VCC (power), 13 GOE1 (in), 14 GND (power), 15 ~{BSCAN} (in), 16 TDI/IN0 (in), 17 I/O0 (io), 18 I/O1 (io), 19 I/O2 (io), 20 I/O3 (io), 21 NC, 22 I/O4 (io), 23 I/O5 (io), 24 I/O6 (io), 25 NC, 26 I/O7 (io), 27 I/O8 (io), 28 I/O9 (io), 29 I/O10 (io), 30 I/O11 (io), 31 NC, 32 I/O12 (io), 33 I/O13 (io), 34 I/O14 (io), 35 I/O15 (io), 36 VCC (power), 37 TMS/IN1 (in), 38 NC, 39 GND (power), 40 I/O16 (io), 41 I/O17 (io), 42 I/O18 (io), 43 I/O19 (io), 44 NC, 45 I/O20 (io), 46 I/O21 (io), 47 I/O22 (io), 48 I/O23 (io), 49 I/O24 (io), 50 NC, 51 I/O25 (io), 52 I/O26 (io), 53 I/O27 (io), 54 NC, 55 I/O28 (io), 56 I/O29 (io), 57 I/O30 (io), 58 I/O31 (io), 59 TCK/IN3 (in), 60 Y2 (in), 61 GND (power), 62 GOE0 (in), 63 VCC (power), 64 NC, 65 Y1 (in), 66 NC, 67 I/O32 (io), 68 I/O33 (io), 69 I/O34 (io), 70 I/O35 (io), 71 NC, 72 I/O36 (io), 73 I/O37 (io), 74 I/O38 (io), 75 NC, 76 I/O39 (io), 77 I/O40 (io), 78 I/O41 (io), 79 I/O42 (io), 80 I/O43 (io), 81 NC, 82 I/O44 (io), 83 I/O45 (io), 84 I/O46 (io), 85 I/O47 (io), 86 GND (power), 87 TDO/IN2 (io), 88 NC, 89 VCC (power), 90 I/O48 (io), 91 I/O49 (io), 92 I/O50 (io), 93 I/O51 (io), 94 NC, 95 I/O52 (io), 96 I/O53 (io), 97 I/O54 (io), 98 I/O55 (io), 99 I/O56 (io), 100 NC

## ispLSI2064VE-135LT100I
designator U?
3.3V In-System Programmable High Density SuperFAST PLD
footprint TQFP100_N (Thin QFP, 100-Leads, Body 14x14mm, Pitch 0.5mm, IPC Medium Density)
footprint TQFP100_L (Thin QFP, 100-Leads, Body 14x14mm, Pitch 0.5mm, IPC High Density)
footprint TQFP100_M (Thin QFP, 100-Leads, Body 14x14mm, Pitch 0.5mm, IPC Low Density)
3D model 2064VE-TQFP100 (100-Pin Thin Quad Flat Pack (TQFP100))
pins: 1 I/O57 (io), 2 I/O58 (io), 3 I/O59 (io), 4 NC, 5 I/O60 (io), 6 I/O61 (io), 7 I/O62 (io), 8 I/O63 (io), 9 NC, 10 Y0 (in), 11 ~{RESET} (in), 12 VCC (power), 13 GOE1 (in), 14 GND (power), 15 ~{BSCAN} (in), 16 TDI/IN0 (in), 17 I/O0 (io), 18 I/O1 (io), 19 I/O2 (io), 20 I/O3 (io), 21 NC, 22 I/O4 (io), 23 I/O5 (io), 24 I/O6 (io), 25 NC, 26 I/O7 (io), 27 I/O8 (io), 28 I/O9 (io), 29 I/O10 (io), 30 I/O11 (io), 31 NC, 32 I/O12 (io), 33 I/O13 (io), 34 I/O14 (io), 35 I/O15 (io), 36 VCC (power), 37 TMS/IN1 (in), 38 NC, 39 GND (power), 40 I/O16 (io), 41 I/O17 (io), 42 I/O18 (io), 43 I/O19 (io), 44 NC, 45 I/O20 (io), 46 I/O21 (io), 47 I/O22 (io), 48 I/O23 (io), 49 I/O24 (io), 50 NC, 51 I/O25 (io), 52 I/O26 (io), 53 I/O27 (io), 54 NC, 55 I/O28 (io), 56 I/O29 (io), 57 I/O30 (io), 58 I/O31 (io), 59 TCK/IN3 (in), 60 Y2 (in), 61 GND (power), 62 GOE0 (in), 63 VCC (power), 64 NC, 65 Y1 (in), 66 NC, 67 I/O32 (io), 68 I/O33 (io), 69 I/O34 (io), 70 I/O35 (io), 71 NC, 72 I/O36 (io), 73 I/O37 (io), 74 I/O38 (io), 75 NC, 76 I/O39 (io), 77 I/O40 (io), 78 I/O41 (io), 79 I/O42 (io), 80 I/O43 (io), 81 NC, 82 I/O44 (io), 83 I/O45 (io), 84 I/O46 (io), 85 I/O47 (io), 86 GND (power), 87 TDO/IN2 (io), 88 NC, 89 VCC (power), 90 I/O48 (io), 91 I/O49 (io), 92 I/O50 (io), 93 I/O51 (io), 94 NC, 95 I/O52 (io), 96 I/O53 (io), 97 I/O54 (io), 98 I/O55 (io), 99 I/O56 (io), 100 NC

## ispLSI2064VE-200LB100
designator U?
3.3V In-System Programmable High Density SuperFAST PLD
footprint caBGA100 (BGA, 100-Leads, Body 10x10mm, Pitch 0.8mm)
3D model 2064VE-caBGA100 (100-Ball Chip Array Ball Grid Array (caBGA100))
pins: A1 I/O57 (io), A2 I/O55 (io), A3 I/O52 (io), A4 I/O50 (io), A5 VCC (power), A6 NC, A7 I/O46 (io), A8 NC, A9 I/O41 (io), A10 I/O39 (io), B1 I/O59 (io), B2 I/O58 (io), B3 I/O56 (io), B4 I/O54 (io), B5 I/O49 (io), B6 TDO/IN2 (io), B7 GND (power), B8 I/O43 (io), B9 I/O40 (io), B10 I/O37 (io), C1 I/O61 (io), C2 I/O60 (io), C3 NC, C4 NC, C5 I/O51 (io), C6 I/O47 (io), C7 I/O45 (io), C8 I/O42 (io), C9 I/O38 (io), C10 I/O35 (io), D1 NC, D2 ~{RESET} (in), D3 I/O63 (io), D4 I/O62 (io), D5 I/O53 (io), D6 NC, D7 I/O44 (io), D8 NC, D9 I/O36 (io), D10 I/O32 (io), E1 GOE1 (in), E2 VCC (power), E3 Y0 (in), E4 I/O2 (io), E5 ~{BSCAN} (in), E6 I/O48 (io), E7 NC, E8 I/O33 (io), E9 NC, E10 NC, F1 GND (power), F2 TDI/IN0 (in), F3 I/O1 (io), F4 NC, F5 I/O16 (io), F6 Y1 (in), F7 I/O34 (io), F8 Y2 (in), F9 GOE0 (in), F10 VCC (power), G1 I/O0 (io), G2 I/O4 (io), G3 NC, G4 I/O12 (io), G5 NC, G6 I/O21 (io), G7 I/O30 (io), G8 I/O31 (io), G9 GND (power), G10 TCK/IN3 (in), H1 I/O3 (io), H2 I/O6 (io), H3 I/O10 (io), H4 I/O13 (io), H5 I/O15 (io), H6 I/O19 (io), H7 NC, H8 NC, H9 I/O28 (io), H10 I/O29 (io), J1 I/O5 (io), J2 I/O8 (io), J3 I/O11 (io), J4 VCC (power), J5 TMS/IN1 (in), J6 I/O17 (io), J7 I/O22 (io), J8 I/O24 (io), J9 I/O26 (io), J10 I/O27 (io), K1 I/O7 (io), K2 I/O9 (io), K3 NC, K4 I/O14 (io), K5 NC, K6 GND (power), K7 I/O18 (io), K8 I/O20 (io), K9 I/O23 (io), K10 I/O25 (io)

## ispLSI2064VE-200LJ44
designator U?
3.3V In-System Programmable High Density SuperFAST PLD
footprint PLCC44_N (Leaded Chip Carrier, 44-Leads, Body 16.6x16.6mm, Pitch 1.27mm, IPC Medium Density)
footprint PLCC44_L (Leaded Chip Carrier, 44-Leads, Body 16.6x16.6mm, Pitch 1.27mm, IPC High Density)
footprint PLCC44_M (Leaded Chip Carrier, 44-Leads, Body 16.6x16.6mm, Pitch 1.27mm, IPC Low Density)
3D model 2064VE-PLCC44 (44-Pin Leaded Chip Carrier 1.27 mm Pitch)
pins: 1 GND (power), 2 GOE0/IN3 (in), 3 I/O24 (io), 4 I/O25 (io), 5 I/O26 (io), 6 I/O27 (io), 7 I/O28 (io), 8 I/O29 (io), 9 I/O30 (io), 10 I/O31 (io), 11 GOE1/Y0 (in), 12 VCC (power), 13 ~{BSCAN} (in), 14 TDI/IN0 (in), 15 I/O0 (io), 16 I/O1 (io), 17 I/O2 (io), 18 I/O3 (io), 19 I/O4 (io), 20 I/O5 (io), 21 I/O6 (io), 22 I/O7 (io), 23 GND (power), 24 TDO/IN1 (io), 25 I/O8 (io), 26 I/O9 (io), 27 I/O10 (io), 28 I/O11 (io), 29 I/O12 (io), 30 I/O13 (io), 31 I/O14 (io), 32 I/O15 (io), 33 TCK/Y2 (in), 34 VCC (power), 35 ~{RESET} /Y1 (in), 36 TMS/IN2 (in), 37 I/O16 (io), 38 I/O17 (io), 39 I/O18 (io), 40 I/O19 (io), 41 I/O20 (io), 42 I/O21 (io), 43 I/O22 (io), 44 I/O23 (io)

## ispLSI2064VE-200LT44
designator U?
3.3V In-System Programmable High Density SuperFAST PLD
footprint TQFP44_N (Thin QFP, 44-Leads, Body 10x10mm, Pitch 0.8mm, IPC Medium Density)
footprint TQFP44_L (Thin QFP, 44-Leads, Body 10x10mm, Pitch 0.8mm, IPC High Density)
footprint TQFP44_M (Thin QFP, 44-Leads, Body 10x10mm, Pitch 0.8mm, IPC Low Density)
3D model 2064VE-TQFP44 (44-Pin Thin Quad Flat Pack 0.8 mm Pitch)
pins: 1 I/O28 (io), 2 I/O29 (io), 3 I/O30 (io), 4 I/O31 (io), 5 GOE1/Y0 (in), 6 VCC (power), 7 ~{BSCAN} (in), 8 TDI/IN0 (in), 9 I/O0 (io), 10 I/O1 (io), 11 I/O2 (io), 12 I/O3 (io), 13 I/O4 (io), 14 I/O5 (io), 15 I/O6 (io), 16 I/O7 (io), 17 GND (power), 18 TDO/IN1 (io), 19 I/O8 (io), 20 I/O9 (io), 21 I/O10 (io), 22 I/O11 (io), 23 I/O12 (io), 24 I/O13 (io), 25 I/O14 (io), 26 I/O15 (io), 27 TCK/Y2 (in), 28 VCC (power), 29 ~{RESET} /Y1 (in), 30 TMS/IN2 (in), 31 I/O16 (io), 32 I/O17 (io), 33 I/O18 (io), 34 I/O19 (io), 35 I/O20 (io), 36 I/O21 (io), 37 I/O22 (io), 38 I/O23 (io), 39 GND (power), 40 GOE0/IN3 (in), 41 I/O24 (io), 42 I/O25 (io), 43 I/O26 (io), 44 I/O27 (io)

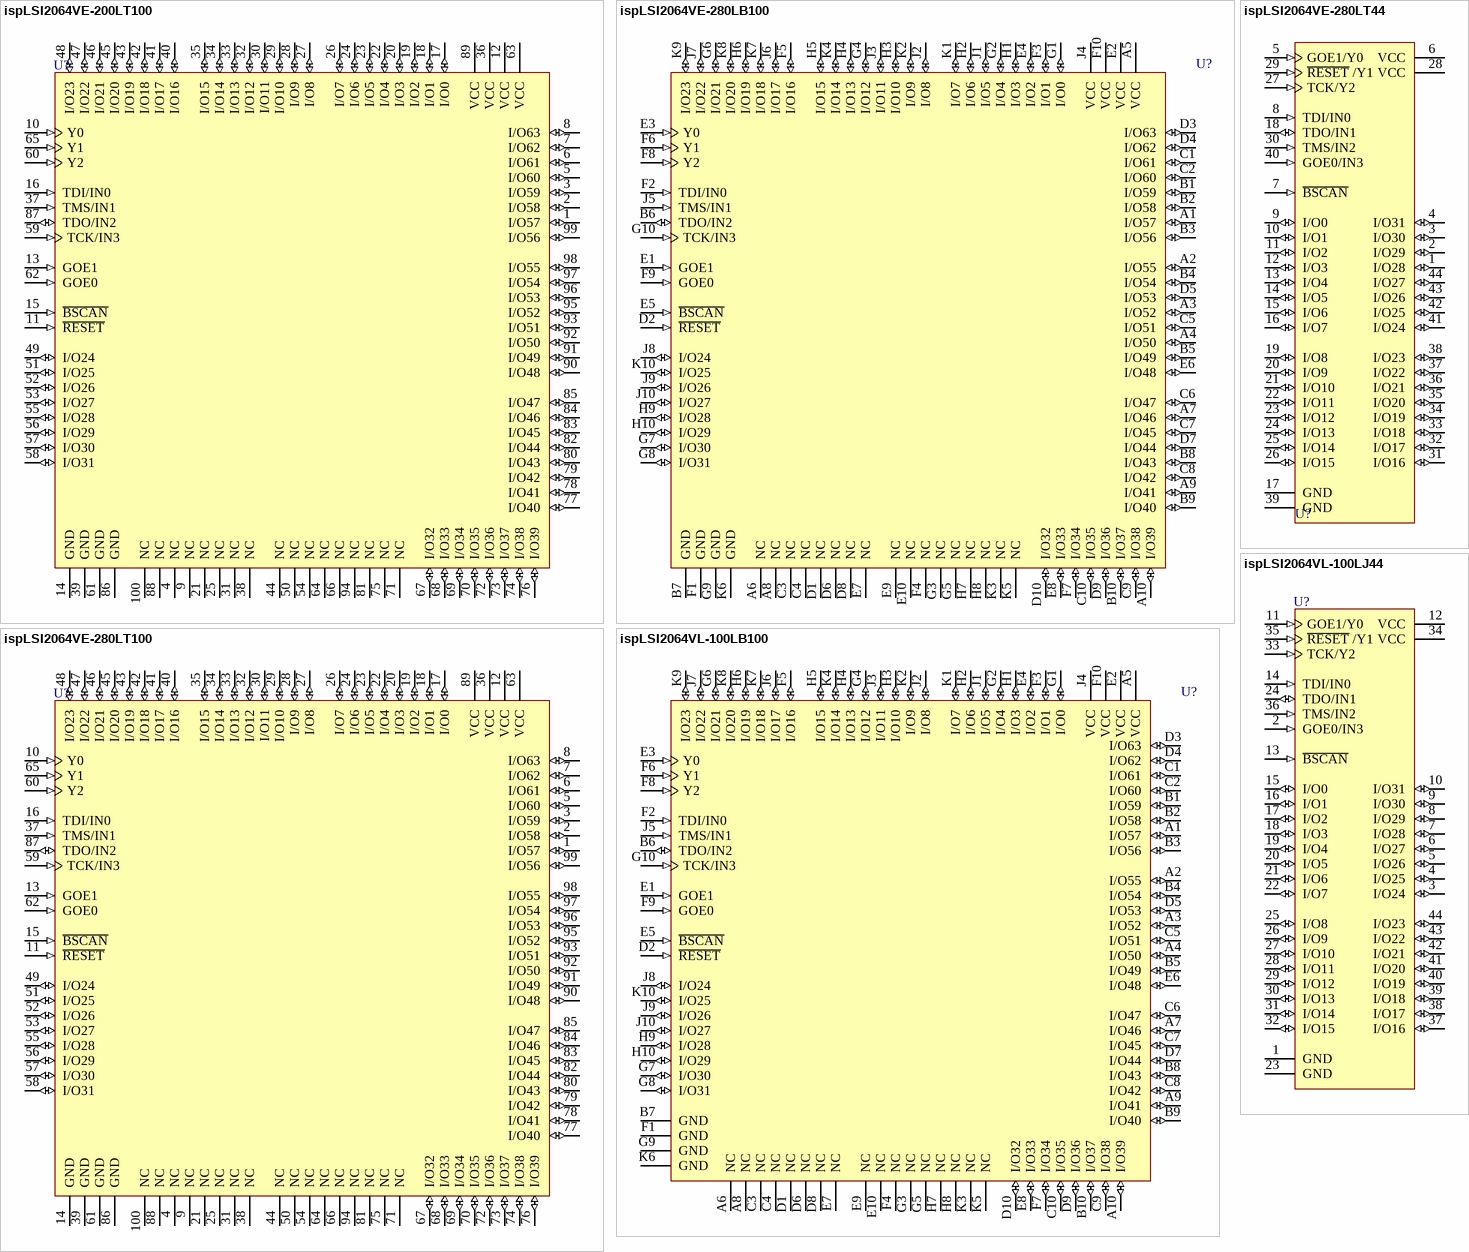
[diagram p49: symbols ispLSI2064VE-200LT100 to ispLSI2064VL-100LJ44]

## ispLSI2064VE-200LT100
designator U?
3.3V In-System Programmable High Density SuperFAST PLD
footprint TQFP100_N (Thin QFP, 100-Leads, Body 14x14mm, Pitch 0.5mm, IPC Medium Density)
footprint TQFP100_L (Thin QFP, 100-Leads, Body 14x14mm, Pitch 0.5mm, IPC High Density)
footprint TQFP100_M (Thin QFP, 100-Leads, Body 14x14mm, Pitch 0.5mm, IPC Low Density)
3D model 2064VE-TQFP100 (100-Pin Thin Quad Flat Pack (TQFP100))
pins: 1 I/O57 (io), 2 I/O58 (io), 3 I/O59 (io), 4 NC, 5 I/O60 (io), 6 I/O61 (io), 7 I/O62 (io), 8 I/O63 (io), 9 NC, 10 Y0 (in), 11 ~{RESET} (in), 12 VCC (power), 13 GOE1 (in), 14 GND (power), 15 ~{BSCAN} (in), 16 TDI/IN0 (in), 17 I/O0 (io), 18 I/O1 (io), 19 I/O2 (io), 20 I/O3 (io), 21 NC, 22 I/O4 (io), 23 I/O5 (io), 24 I/O6 (io), 25 NC, 26 I/O7 (io), 27 I/O8 (io), 28 I/O9 (io), 29 I/O10 (io), 30 I/O11 (io), 31 NC, 32 I/O12 (io), 33 I/O13 (io), 34 I/O14 (io), 35 I/O15 (io), 36 VCC (power), 37 TMS/IN1 (in), 38 NC, 39 GND (power), 40 I/O16 (io), 41 I/O17 (io), 42 I/O18 (io), 43 I/O19 (io), 44 NC, 45 I/O20 (io), 46 I/O21 (io), 47 I/O22 (io), 48 I/O23 (io), 49 I/O24 (io), 50 NC, 51 I/O25 (io), 52 I/O26 (io), 53 I/O27 (io), 54 NC, 55 I/O28 (io), 56 I/O29 (io), 57 I/O30 (io), 58 I/O31 (io), 59 TCK/IN3 (in), 60 Y2 (in), 61 GND (power), 62 GOE0 (in), 63 VCC (power), 64 NC, 65 Y1 (in), 66 NC, 67 I/O32 (io), 68 I/O33 (io), 69 I/O34 (io), 70 I/O35 (io), 71 NC, 72 I/O36 (io), 73 I/O37 (io), 74 I/O38 (io), 75 NC, 76 I/O39 (io), 77 I/O40 (io), 78 I/O41 (io), 79 I/O42 (io), 80 I/O43 (io), 81 NC, 82 I/O44 (io), 83 I/O45 (io), 84 I/O46 (io), 85 I/O47 (io), 86 GND (power), 87 TDO/IN2 (io), 88 NC, 89 VCC (power), 90 I/O48 (io), 91 I/O49 (io), 92 I/O50 (io), 93 I/O51 (io), 94 NC, 95 I/O52 (io), 96 I/O53 (io), 97 I/O54 (io), 98 I/O55 (io), 99 I/O56 (io), 100 NC

## ispLSI2064VE-280LB100
designator U?
3.3V In-System Programmable High Density SuperFAST PLD
footprint caBGA100 (BGA, 100-Leads, Body 10x10mm, Pitch 0.8mm)
3D model 2064VE-caBGA100 (100-Ball Chip Array Ball Grid Array (caBGA100))
pins: A1 I/O57 (io), A2 I/O55 (io), A3 I/O52 (io), A4 I/O50 (io), A5 VCC (power), A6 NC, A7 I/O46 (io), A8 NC, A9 I/O41 (io), A10 I/O39 (io), B1 I/O59 (io), B2 I/O58 (io), B3 I/O56 (io), B4 I/O54 (io), B5 I/O49 (io), B6 TDO/IN2 (io), B7 GND (power), B8 I/O43 (io), B9 I/O40 (io), B10 I/O37 (io), C1 I/O61 (io), C2 I/O60 (io), C3 NC, C4 NC, C5 I/O51 (io), C6 I/O47 (io), C7 I/O45 (io), C8 I/O42 (io), C9 I/O38 (io), C10 I/O35 (io), D1 NC, D2 ~{RESET} (in), D3 I/O63 (io), D4 I/O62 (io), D5 I/O53 (io), D6 NC, D7 I/O44 (io), D8 NC, D9 I/O36 (io), D10 I/O32 (io), E1 GOE1 (in), E2 VCC (power), E3 Y0 (in), E4 I/O2 (io), E5 ~{BSCAN} (in), E6 I/O48 (io), E7 NC, E8 I/O33 (io), E9 NC, E10 NC, F1 GND (power), F2 TDI/IN0 (in), F3 I/O1 (io), F4 NC, F5 I/O16 (io), F6 Y1 (in), F7 I/O34 (io), F8 Y2 (in), F9 GOE0 (in), F10 VCC (power), G1 I/O0 (io), G2 I/O4 (io), G3 NC, G4 I/O12 (io), G5 NC, G6 I/O21 (io), G7 I/O30 (io), G8 I/O31 (io), G9 GND (power), G10 TCK/IN3 (in), H1 I/O3 (io), H2 I/O6 (io), H3 I/O10 (io), H4 I/O13 (io), H5 I/O15 (io), H6 I/O19 (io), H7 NC, H8 NC, H9 I/O28 (io), H10 I/O29 (io), J1 I/O5 (io), J2 I/O8 (io), J3 I/O11 (io), J4 VCC (power), J5 TMS/IN1 (in), J6 I/O17 (io), J7 I/O22 (io), J8 I/O24 (io), J9 I/O26 (io), J10 I/O27 (io), K1 I/O7 (io), K2 I/O9 (io), K3 NC, K4 I/O14 (io), K5 NC, K6 GND (power), K7 I/O18 (io), K8 I/O20 (io), K9 I/O23 (io), K10 I/O25 (io)

## ispLSI2064VE-280LT44
designator U?
3.3V In-System Programmable High Density SuperFAST PLD
footprint TQFP44_N (Thin QFP, 44-Leads, Body 10x10mm, Pitch 0.8mm, IPC Medium Density)
footprint TQFP44_L (Thin QFP, 44-Leads, Body 10x10mm, Pitch 0.8mm, IPC High Density)
footprint TQFP44_M (Thin QFP, 44-Leads, Body 10x10mm, Pitch 0.8mm, IPC Low Density)
3D model 2064VE-TQFP44 (44-Pin Thin Quad Flat Pack 0.8 mm Pitch)
pins: 1 I/O28 (io), 2 I/O29 (io), 3 I/O30 (io), 4 I/O31 (io), 5 GOE1/Y0 (in), 6 VCC (power), 7 ~{BSCAN} (in), 8 TDI/IN0 (in), 9 I/O0 (io), 10 I/O1 (io), 11 I/O2 (io), 12 I/O3 (io), 13 I/O4 (io), 14 I/O5 (io), 15 I/O6 (io), 16 I/O7 (io), 17 GND (power), 18 TDO/IN1 (io), 19 I/O8 (io), 20 I/O9 (io), 21 I/O10 (io), 22 I/O11 (io), 23 I/O12 (io), 24 I/O13 (io), 25 I/O14 (io), 26 I/O15 (io), 27 TCK/Y2 (in), 28 VCC (power), 29 ~{RESET} /Y1 (in), 30 TMS/IN2 (in), 31 I/O16 (io), 32 I/O17 (io), 33 I/O18 (io), 34 I/O19 (io), 35 I/O20 (io), 36 I/O21 (io), 37 I/O22 (io), 38 I/O23 (io), 39 GND (power), 40 GOE0/IN3 (in), 41 I/O24 (io), 42 I/O25 (io), 43 I/O26 (io), 44 I/O27 (io)

## ispLSI2064VE-280LT100
designator U?
3.3V In-System Programmable High Density SuperFAST PLD
footprint TQFP100_N (Thin QFP, 100-Leads, Body 14x14mm, Pitch 0.5mm, IPC Medium Density)
footprint TQFP100_L (Thin QFP, 100-Leads, Body 14x14mm, Pitch 0.5mm, IPC High Density)
footprint TQFP100_M (Thin QFP, 100-Leads, Body 14x14mm, Pitch 0.5mm, IPC Low Density)
3D model 2064VE-TQFP100 (100-Pin Thin Quad Flat Pack (TQFP100))
pins: 1 I/O57 (io), 2 I/O58 (io), 3 I/O59 (io), 4 NC, 5 I/O60 (io), 6 I/O61 (io), 7 I/O62 (io), 8 I/O63 (io), 9 NC, 10 Y0 (in), 11 ~{RESET} (in), 12 VCC (power), 13 GOE1 (in), 14 GND (power), 15 ~{BSCAN} (in), 16 TDI/IN0 (in), 17 I/O0 (io), 18 I/O1 (io), 19 I/O2 (io), 20 I/O3 (io), 21 NC, 22 I/O4 (io), 23 I/O5 (io), 24 I/O6 (io), 25 NC, 26 I/O7 (io), 27 I/O8 (io), 28 I/O9 (io), 29 I/O10 (io), 30 I/O11 (io), 31 NC, 32 I/O12 (io), 33 I/O13 (io), 34 I/O14 (io), 35 I/O15 (io), 36 VCC (power), 37 TMS/IN1 (in), 38 NC, 39 GND (power), 40 I/O16 (io), 41 I/O17 (io), 42 I/O18 (io), 43 I/O19 (io), 44 NC, 45 I/O20 (io), 46 I/O21 (io), 47 I/O22 (io), 48 I/O23 (io), 49 I/O24 (io), 50 NC, 51 I/O25 (io), 52 I/O26 (io), 53 I/O27 (io), 54 NC, 55 I/O28 (io), 56 I/O29 (io), 57 I/O30 (io), 58 I/O31 (io), 59 TCK/IN3 (in), 60 Y2 (in), 61 GND (power), 62 GOE0 (in), 63 VCC (power), 64 NC, 65 Y1 (in), 66 NC, 67 I/O32 (io), 68 I/O33 (io), 69 I/O34 (io), 70 I/O35 (io), 71 NC, 72 I/O36 (io), 73 I/O37 (io), 74 I/O38 (io), 75 NC, 76 I/O39 (io), 77 I/O40 (io), 78 I/O41 (io), 79 I/O42 (io), 80 I/O43 (io), 81 NC, 82 I/O44 (io), 83 I/O45 (io), 84 I/O46 (io), 85 I/O47 (io), 86 GND (power), 87 TDO/IN2 (io), 88 NC, 89 VCC (power), 90 I/O48 (io), 91 I/O49 (io), 92 I/O50 (io), 93 I/O51 (io), 94 NC, 95 I/O52 (io), 96 I/O53 (io), 97 I/O54 (io), 98 I/O55 (io), 99 I/O56 (io), 100 NC

## ispLSI2064VL-100LB100
designator U?
2.5V In-System Programmable SuperFAST High Density PLD
footprint caBGA100 (BGA, 100-Leads, Body 10x10mm, Pitch 0.8mm)
3D model 2064VL-caBGA100 (100-Ball Chip Array Ball Grid Array (caBGA100))
pins: A1 I/O57 (io), A2 I/O55 (io), A3 I/O52 (io), A4 I/O50 (io), A5 VCC (power), A6 NC, A7 I/O46 (io), A8 NC, A9 I/O41 (io), A10 I/O39 (io), B1 I/O59 (io), B2 I/O58 (io), B3 I/O56 (io), B4 I/O54 (io), B5 I/O49 (io), B6 TDO/IN2 (io), B7 GND (power), B8 I/O43 (io), B9 I/O40 (io), B10 I/O37 (io), C1 I/O61 (io), C2 I/O60 (io), C3 NC, C4 NC, C5 I/O51 (io), C6 I/O47 (io), C7 I/O45 (io), C8 I/O42 (io), C9 I/O38 (io), C10 I/O35 (io), D1 NC, D2 ~{RESET} (in), D3 I/O63 (io), D4 I/O62 (io), D5 I/O53 (io), D6 NC, D7 I/O44 (io), D8 NC, D9 I/O36 (io), D10 I/O32 (io), E1 GOE1 (in), E2 VCC (power), E3 Y0 (in), E4 I/O2 (io), E5 ~{BSCAN} (in), E6 I/O48 (io), E7 NC, E8 I/O33 (io), E9 NC, E10 NC, F1 GND (power), F2 TDI/IN0 (in), F3 I/O1 (io), F4 NC, F5 I/O16 (io), F6 Y1 (in), F7 I/O34 (io), F8 Y2 (in), F9 GOE0 (in), F10 VCC (power), G1 I/O0 (io), G2 I/O4 (io), G3 NC, G4 I/O12 (io), G5 NC, G6 I/O21 (io), G7 I/O30 (io), G8 I/O31 (io), G9 GND (power), G10 TCK/IN3 (in), H1 I/O3 (io), H2 I/O6 (io), H3 I/O10 (io), H4 I/O13 (io), H5 I/O15 (io), H6 I/O19 (io), H7 NC, H8 NC, H9 I/O28 (io), H10 I/O29 (io), J1 I/O5 (io), J2 I/O8 (io), J3 I/O11 (io), J4 VCC (power), J5 TMS/IN1 (in), J6 I/O17 (io), J7 I/O22 (io), J8 I/O24 (io), J9 I/O26 (io), J10 I/O27 (io), K1 I/O7 (io), K2 I/O9 (io), K3 NC, K4 I/O14 (io), K5 NC, K6 GND (power), K7 I/O18 (io), K8 I/O20 (io), K9 I/O23 (io), K10 I/O25 (io)

## ispLSI2064VL-100LJ44
designator U?
2.5V In-System Programmable SuperFAST High Density PLD
footprint PLCC44_N (Leaded Chip Carrier, 44-Leads, Body 16.6x16.6mm, Pitch 1.27mm, IPC Medium Density)
footprint PLCC44_L (Leaded Chip Carrier, 44-Leads, Body 16.6x16.6mm, Pitch 1.27mm, IPC High Density)
footprint PLCC44_M (Leaded Chip Carrier, 44-Leads, Body 16.6x16.6mm, Pitch 1.27mm, IPC Low Density)
3D model 2064VL-PLCC44 (44-Pin Leaded Chip Carrier 1.27 mm Pitch)
pins: 1 GND (power), 2 GOE0/IN3 (in), 3 I/O24 (io), 4 I/O25 (io), 5 I/O26 (io), 6 I/O27 (io), 7 I/O28 (io), 8 I/O29 (io), 9 I/O30 (io), 10 I/O31 (io), 11 GOE1/Y0 (in), 12 VCC (power), 13 ~{BSCAN} (in), 14 TDI/IN0 (in), 15 I/O0 (io), 16 I/O1 (io), 17 I/O2 (io), 18 I/O3 (io), 19 I/O4 (io), 20 I/O5 (io), 21 I/O6 (io), 22 I/O7 (io), 23 GND (power), 24 TDO/IN1 (io), 25 I/O8 (io), 26 I/O9 (io), 27 I/O10 (io), 28 I/O11 (io), 29 I/O12 (io), 30 I/O13 (io), 31 I/O14 (io), 32 I/O15 (io), 33 TCK/Y2 (in), 34 VCC (power), 35 ~{RESET} /Y1 (in), 36 TMS/IN2 (in), 37 I/O16 (io), 38 I/O17 (io), 39 I/O18 (io), 40 I/O19 (io), 41 I/O20 (io), 42 I/O21 (io), 43 I/O22 (io), 44 I/O23 (io)

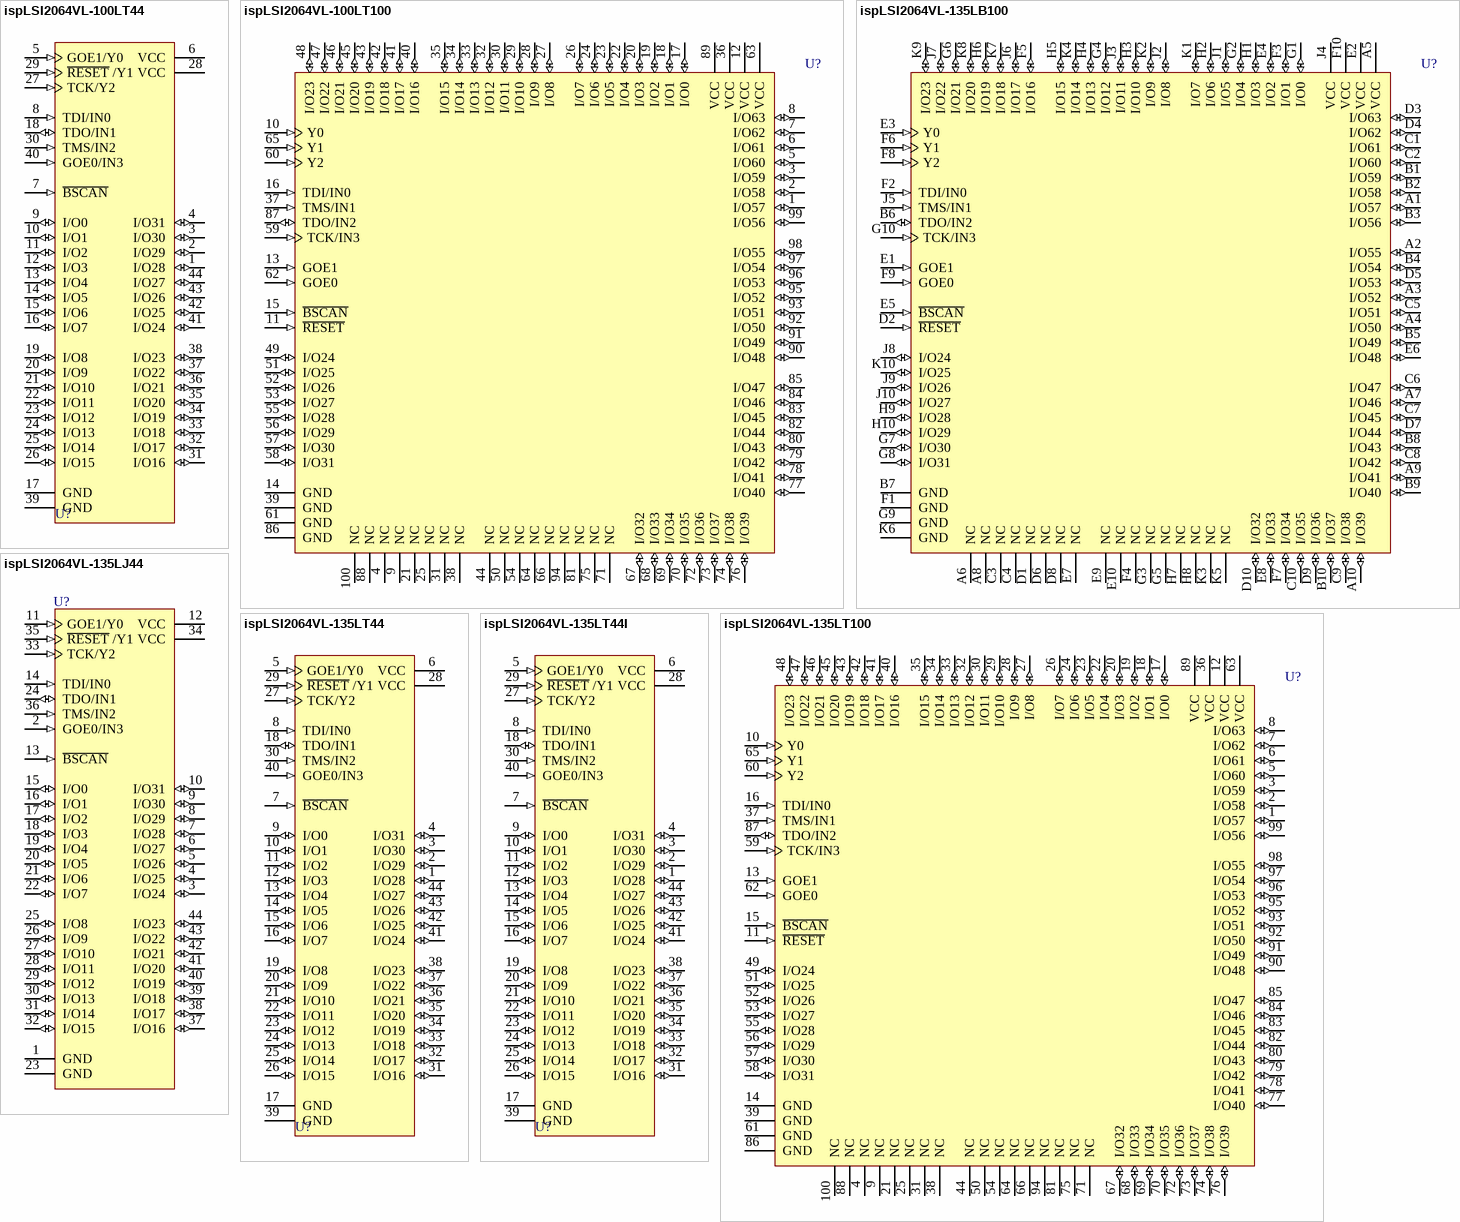
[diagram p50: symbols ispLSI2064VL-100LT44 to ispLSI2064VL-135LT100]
